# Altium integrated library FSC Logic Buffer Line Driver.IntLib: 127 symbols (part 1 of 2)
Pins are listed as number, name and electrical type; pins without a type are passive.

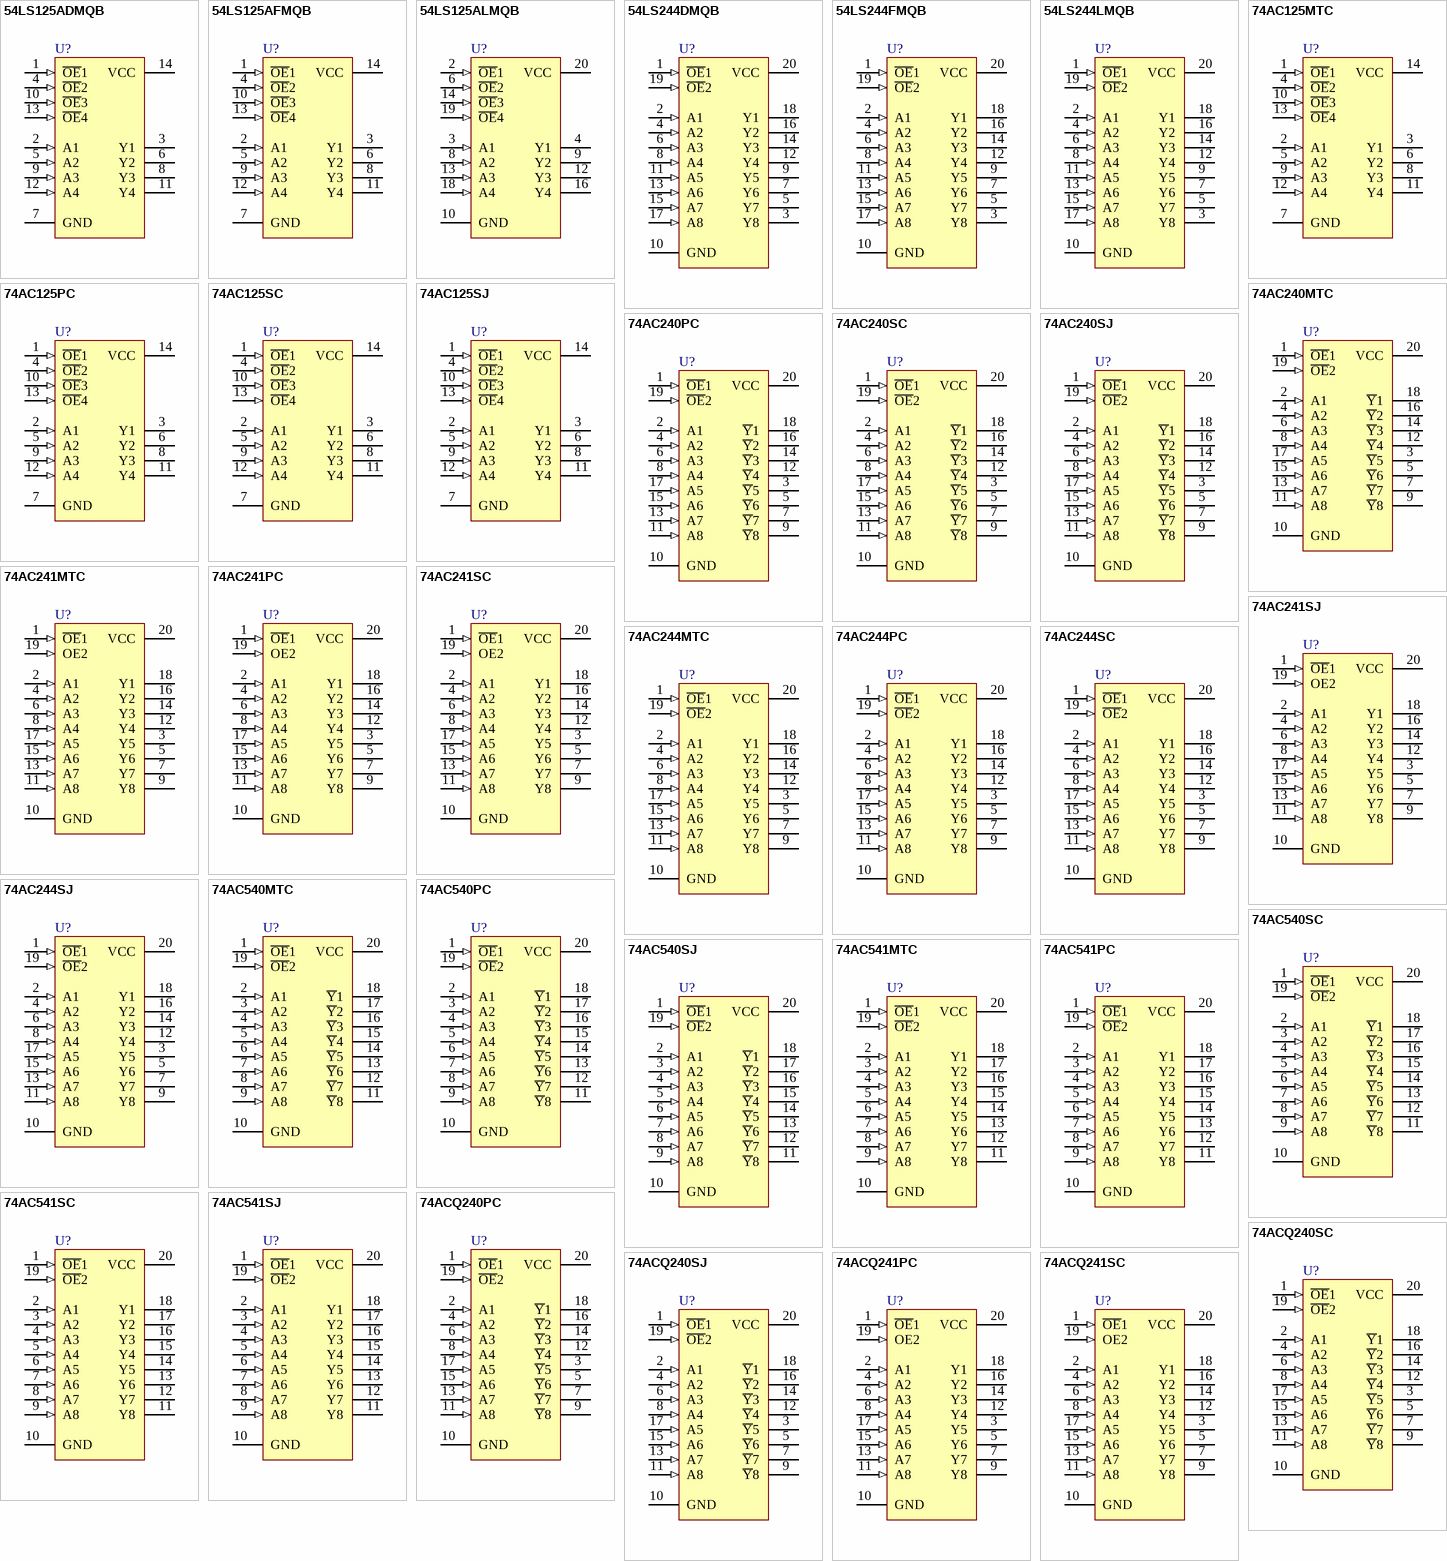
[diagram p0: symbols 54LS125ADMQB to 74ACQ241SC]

## 54LS125ADMQB
designator U?
Quad 3-State Buffer
footprint J14A (DIP, 14-Leads, Row Spacing 7.62mm, Pitch 2.54mm, Body 19.56x6.73mm)
3D model J14A (CerDIP, 14-Pin, Row Spacing 7.62 mm, Pitch 2.54 mm)
simulation model 74LS125 (SIMCODE)
signal-integrity model 54LS125ADMQB
pins: 1 ~{OE}1 (in), 2 A1 (in), 3 Y1 (hiz), 4 ~{OE}2 (in), 5 A2 (in), 6 Y2 (hiz), 7 GND (power), 8 Y3 (hiz), 9 A3 (in), 10 ~{OE}3 (in), 11 Y4 (hiz), 12 A4 (in), 13 ~{OE}4 (in), 14 VCC (power)

## 54LS125AFMQB
designator U?
Quad 3-State Buffer
footprint W14B (DFP; 14 Leads; Body 9.8 x 7.1 mm (LxW max); Pitch 1.27 mm)
3D model W14B (DFP; 14 Leads; Body 9.8 x 7.1 mm (LxW max); Pitch 1.27 mm)
simulation model 74LS125 (SIMCODE)
signal-integrity model 54LS125AFMQB
pins: 1 ~{OE}1 (in), 2 A1 (in), 3 Y1 (hiz), 4 ~{OE}2 (in), 5 A2 (in), 6 Y2 (hiz), 7 GND (power), 8 Y3 (hiz), 9 A3 (in), 10 ~{OE}3 (in), 11 Y4 (hiz), 12 A4 (in), 13 ~{OE}4 (in), 14 VCC (power)

## 54LS125ALMQB
designator U?
Quad 3-State Buffer
footprint E20A (Leadless Chip Carrier; 20 Terminals; Body 8.9 x 8.9 mm)
footprint E20A_N (Leadless Chip Carrier, 20-Leads, Body 8.9x8.9mm, Pitch 1.27mm, IPC Medium Density)
footprint E20A_L (Leadless Chip Carrier, 20-Leads, Body 8.9x8.9mm, Pitch 1.27mm, IPC High Density)
footprint E20A_M (Leadless Chip Carrier, 20-Leads, Body 8.9x8.9mm, Pitch 1.27mm, IPC Low Density)
simulation model 74LS125 (SIMCODE)
signal-integrity model 54LS125ALMQB
pins: 2 ~{OE}1 (in), 3 A1 (in), 4 Y1 (hiz), 6 ~{OE}2 (in), 8 A2 (in), 9 Y2 (hiz), 10 GND (power), 12 Y3 (hiz), 13 A3 (in), 14 ~{OE}3 (in), 16 Y4 (hiz), 18 A4 (in), 19 ~{OE}4 (in), 20 VCC (power)

## 54LS244DMQB
designator U?
Octal 3-State Buffer/Line Driver/Line Receiver
footprint J20A (DIP, 20-Leads, Row Spacing 7.62mm, Pitch 2.54mm, Body 24.62x6.73mm)
3D model J20A (CerDIP, 20-Pin, Row Spacing 7.62 mm, Pitch 2.54 mm)
simulation model 74LS244 (SIMCODE)
signal-integrity model 54LS244DMQB
pins: 1 ~{OE}1 (in), 2 A1 (in), 3 Y8 (hiz), 4 A2 (in), 5 Y7 (hiz), 6 A3 (in), 7 Y6 (hiz), 8 A4 (in), 9 Y5 (hiz), 10 GND (power), 11 A5 (in), 12 Y4 (hiz), 13 A6 (in), 14 Y3 (hiz), 15 A7 (in), 16 Y2 (hiz), 17 A8 (in), 18 Y1 (hiz), 19 ~{OE}2 (in), 20 VCC (power)

## 54LS244FMQB
designator U?
Octal 3-State Buffer/Line Driver/Line Receiver
footprint W20A (DFP; 20 Leads; Body 13.7 x 7.2 mm (LxW max); Pitch 1.27 mm)
3D model W20A (DFP; 20 Leads; Body 13.7 x 7.2 mm (LxW max); Pitch 1.27 mm)
simulation model 74LS244 (SIMCODE)
signal-integrity model 54LS244FMQB
pins: 1 ~{OE}1 (in), 2 A1 (in), 3 Y8 (hiz), 4 A2 (in), 5 Y7 (hiz), 6 A3 (in), 7 Y6 (hiz), 8 A4 (in), 9 Y5 (hiz), 10 GND (power), 11 A5 (in), 12 Y4 (hiz), 13 A6 (in), 14 Y3 (hiz), 15 A7 (in), 16 Y2 (hiz), 17 A8 (in), 18 Y1 (hiz), 19 ~{OE}2 (in), 20 VCC (power)

## 54LS244LMQB
designator U?
Octal 3-State Buffer/Line Driver/Line Receiver
footprint E20A (Leadless Chip Carrier; 20 Terminals; Body 8.9 x 8.9 mm)
footprint E20A_N (Leadless Chip Carrier, 20-Leads, Body 8.9x8.9mm, Pitch 1.27mm, IPC Medium Density)
footprint E20A_L (Leadless Chip Carrier, 20-Leads, Body 8.9x8.9mm, Pitch 1.27mm, IPC High Density)
footprint E20A_M (Leadless Chip Carrier, 20-Leads, Body 8.9x8.9mm, Pitch 1.27mm, IPC Low Density)
simulation model 74LS244 (SIMCODE)
signal-integrity model 54LS244LMQB
pins: 1 ~{OE}1 (in), 2 A1 (in), 3 Y8 (hiz), 4 A2 (in), 5 Y7 (hiz), 6 A3 (in), 7 Y6 (hiz), 8 A4 (in), 9 Y5 (hiz), 10 GND (power), 11 A5 (in), 12 Y4 (hiz), 13 A6 (in), 14 Y3 (hiz), 15 A7 (in), 16 Y2 (hiz), 17 A8 (in), 18 Y1 (hiz), 19 ~{OE}2 (in), 20 VCC (power)

## 74AC125MTC
designator U?
Quad Buffer with 3-State Output
footprint MTC14_N (TSOP, 14-Leads, Body 5x4.4mm, Pitch 0.65mm, IPC Medium Density)
footprint MTC14_L (TSOP, 14-Leads, Body 5x4.4mm, Pitch 0.65mm, IPC High Density)
footprint MTC14_M (TSOP, 14-Leads, Body 5x4.4mm, Pitch 0.65mm, IPC Low Density)
3D model MTC14 (14-Pin Thin Small Outline Package 0.65 mm Pitch)
signal-integrity model 74AC125MTC
pins: 1 ~{OE}1 (in), 2 A1 (in), 3 Y1 (hiz), 4 ~{OE}2 (in), 5 A2 (in), 6 Y2 (hiz), 7 GND (power), 8 Y3 (hiz), 9 A3 (in), 10 ~{OE}3 (in), 11 Y4 (hiz), 12 A4 (in), 13 ~{OE}4 (in), 14 VCC (power)

## 74AC125PC
designator U?
Quad Buffer with 3-State Output
footprint N14A (DIP, 14-Leads, Row Spacing 7.62mm, Pitch 2.54mm, Body 19.18x6.35mm)
3D model N14A (DIP, 14-Pin, Row Spacing 7.62 mm, Pitch 2.54 mm)
signal-integrity model 74AC125PC
pins: 1 ~{OE}1 (in), 2 A1 (in), 3 Y1 (hiz), 4 ~{OE}2 (in), 5 A2 (in), 6 Y2 (hiz), 7 GND (power), 8 Y3 (hiz), 9 A3 (in), 10 ~{OE}3 (in), 11 Y4 (hiz), 12 A4 (in), 13 ~{OE}4 (in), 14 VCC (power)

## 74AC125SC
designator U?
Quad Buffer with 3-State Output
footprint M14A_N (SOIC, 14-Leads, Body 8.6x3.9mm, Pitch 1.27mm, IPC Medium Density)
footprint M14A_L (SOIC, 14-Leads, Body 8.6x3.9mm, Pitch 1.27mm, IPC High Density)
footprint M14A_M (SOIC, 14-Leads, Body 8.6x3.9mm, Pitch 1.27mm, IPC Low Density)
3D model M14A (14-Pin Small Outline Integrated Circuit 1.27 mm Pitch)
signal-integrity model 74AC125SC
pins: 1 ~{OE}1 (in), 2 A1 (in), 3 Y1 (hiz), 4 ~{OE}2 (in), 5 A2 (in), 6 Y2 (hiz), 7 GND (power), 8 Y3 (hiz), 9 A3 (in), 10 ~{OE}3 (in), 11 Y4 (hiz), 12 A4 (in), 13 ~{OE}4 (in), 14 VCC (power)

## 74AC125SJ
designator U?
Quad Buffer with 3-State Output
footprint M14D_N (SOP, 14-Leads, Body 10.1x5.3mm, Pitch 1.27mm, IPC Medium Density)
footprint M14D_L (SOP, 14-Leads, Body 10.1x5.3mm, Pitch 1.27mm, IPC High Density)
footprint M14D_M (SOP, 14-Leads, Body 10.1x5.3mm, Pitch 1.27mm, IPC Low Density)
3D model M14D (14-Pin Small Outline Package 1.27 mm Pitch)
signal-integrity model 74AC125SJ
pins: 1 ~{OE}1 (in), 2 A1 (in), 3 Y1 (hiz), 4 ~{OE}2 (in), 5 A2 (in), 6 Y2 (hiz), 7 GND (power), 8 Y3 (hiz), 9 A3 (in), 10 ~{OE}3 (in), 11 Y4 (hiz), 12 A4 (in), 13 ~{OE}4 (in), 14 VCC (power)

## 74AC240MTC
designator U?
Octal Buffer/Line Driver with 3-State Output
footprint MTC20_N (TSOP, 20-Leads, Body 6.5x4.4mm, Pitch 0.65mm, IPC Medium Density)
footprint MTC20_L (TSOP, 20-Leads, Body 6.5x4.4mm, Pitch 0.65mm, IPC High Density)
footprint MTC20_M (TSOP, 20-Leads, Body 6.5x4.4mm, Pitch 0.65mm, IPC Low Density)
3D model MTC20 (20-Pin Thin Small Outline Package 0.65 mm Pitch)
signal-integrity model 74AC240MTC
pins: 1 ~{OE}1 (in), 2 A1 (in), 3 ~{Y}5 (hiz), 4 A2 (in), 5 ~{Y}6 (hiz), 6 A3 (in), 7 ~{Y}7 (hiz), 8 A4 (in), 9 ~{Y}8 (hiz), 10 GND (power), 11 A8 (in), 12 ~{Y}4 (hiz), 13 A7 (in), 14 ~{Y}3 (hiz), 15 A6 (in), 16 ~{Y}2 (hiz), 17 A5 (in), 18 ~{Y}1 (hiz), 19 ~{OE}2 (in), 20 VCC (power)

## 74AC240PC
designator U?
Octal Buffer/Line Driver with 3-State Output
footprint N20A (DIP, 20-Leads, Row Spacing 7.62mm, Pitch 2.54mm, Body 26.07x6.6mm)
3D model N20A (DIP, 20-Pin, Row Spacing 7.62 mm, Pitch 2.54 mm)
signal-integrity model 74AC240PC
pins: 1 ~{OE}1 (in), 2 A1 (in), 3 ~{Y}5 (hiz), 4 A2 (in), 5 ~{Y}6 (hiz), 6 A3 (in), 7 ~{Y}7 (hiz), 8 A4 (in), 9 ~{Y}8 (hiz), 10 GND (power), 11 A8 (in), 12 ~{Y}4 (hiz), 13 A7 (in), 14 ~{Y}3 (hiz), 15 A6 (in), 16 ~{Y}2 (hiz), 17 A5 (in), 18 ~{Y}1 (hiz), 19 ~{OE}2 (in), 20 VCC (power)

## 74AC240SC
designator U?
Octal Buffer/Line Driver with 3-State Output
footprint M20B_N (SOIC, 20-Leads, Body 12.8x7.5mm, Pitch 1.27mm, IPC Medium Density)
footprint M20B_L (SOIC, 20-Leads, Body 12.8x7.5mm, Pitch 1.27mm, IPC High Density)
footprint M20B_M (SOIC, 20-Leads, Body 12.8x7.5mm, Pitch 1.27mm, IPC Low Density)
3D model M20B (20-Pin Small Outline Integrated Circuit 1.27 mm Pitch)
signal-integrity model 74AC240SC
pins: 1 ~{OE}1 (in), 2 A1 (in), 3 ~{Y}5 (hiz), 4 A2 (in), 5 ~{Y}6 (hiz), 6 A3 (in), 7 ~{Y}7 (hiz), 8 A4 (in), 9 ~{Y}8 (hiz), 10 GND (power), 11 A8 (in), 12 ~{Y}4 (hiz), 13 A7 (in), 14 ~{Y}3 (hiz), 15 A6 (in), 16 ~{Y}2 (hiz), 17 A5 (in), 18 ~{Y}1 (hiz), 19 ~{OE}2 (in), 20 VCC (power)

## 74AC240SJ
designator U?
Octal Buffer/Line Driver with 3-State Output
footprint M20D_N (SOP, 20-Leads, Body 12.6x5.3mm, Pitch 1.27mm, IPC Medium Density)
footprint M20D_L (SOP, 20-Leads, Body 12.6x5.3mm, Pitch 1.27mm, IPC High Density)
footprint M20D_M (SOP, 20-Leads, Body 12.6x5.3mm, Pitch 1.27mm, IPC Low Density)
3D model M20D (20-Pin Small Outline Package 1.27 mm Pitch)
signal-integrity model 74AC240SJ
pins: 1 ~{OE}1 (in), 2 A1 (in), 3 ~{Y}5 (hiz), 4 A2 (in), 5 ~{Y}6 (hiz), 6 A3 (in), 7 ~{Y}7 (hiz), 8 A4 (in), 9 ~{Y}8 (hiz), 10 GND (power), 11 A8 (in), 12 ~{Y}4 (hiz), 13 A7 (in), 14 ~{Y}3 (hiz), 15 A6 (in), 16 ~{Y}2 (hiz), 17 A5 (in), 18 ~{Y}1 (hiz), 19 ~{OE}2 (in), 20 VCC (power)

## 74AC241MTC
designator U?
Octal Buffer/Line Driver with 3-State Output
footprint MTC20_N (TSOP, 20-Leads, Body 6.5x4.4mm, Pitch 0.65mm, IPC Medium Density)
footprint MTC20_L (TSOP, 20-Leads, Body 6.5x4.4mm, Pitch 0.65mm, IPC High Density)
footprint MTC20_M (TSOP, 20-Leads, Body 6.5x4.4mm, Pitch 0.65mm, IPC Low Density)
3D model MTC20 (20-Pin Thin Small Outline Package 0.65 mm Pitch)
signal-integrity model 74AC241MTC
pins: 1 ~{OE}1 (in), 2 A1 (in), 3 Y5 (hiz), 4 A2 (in), 5 Y6 (hiz), 6 A3 (in), 7 Y7 (hiz), 8 A4 (in), 9 Y8 (hiz), 10 GND (power), 11 A8 (in), 12 Y4 (hiz), 13 A7 (in), 14 Y3 (hiz), 15 A6 (in), 16 Y2 (hiz), 17 A5 (in), 18 Y1 (hiz), 19 OE2 (in), 20 VCC (power)

## 74AC241PC
designator U?
Octal Buffer/Line Driver with 3-State Output
footprint N20A (DIP, 20-Leads, Row Spacing 7.62mm, Pitch 2.54mm, Body 26.07x6.6mm)
3D model N20A (DIP, 20-Pin, Row Spacing 7.62 mm, Pitch 2.54 mm)
signal-integrity model 74AC241PC
pins: 1 ~{OE}1 (in), 2 A1 (in), 3 Y5 (hiz), 4 A2 (in), 5 Y6 (hiz), 6 A3 (in), 7 Y7 (hiz), 8 A4 (in), 9 Y8 (hiz), 10 GND (power), 11 A8 (in), 12 Y4 (hiz), 13 A7 (in), 14 Y3 (hiz), 15 A6 (in), 16 Y2 (hiz), 17 A5 (in), 18 Y1 (hiz), 19 OE2 (in), 20 VCC (power)

## 74AC241SC
designator U?
Octal Buffer/Line Driver with 3-State Output
footprint M20B_N (SOIC, 20-Leads, Body 12.8x7.5mm, Pitch 1.27mm, IPC Medium Density)
footprint M20B_L (SOIC, 20-Leads, Body 12.8x7.5mm, Pitch 1.27mm, IPC High Density)
footprint M20B_M (SOIC, 20-Leads, Body 12.8x7.5mm, Pitch 1.27mm, IPC Low Density)
3D model M20B (20-Pin Small Outline Integrated Circuit 1.27 mm Pitch)
signal-integrity model 74AC241SC
pins: 1 ~{OE}1 (in), 2 A1 (in), 3 Y5 (hiz), 4 A2 (in), 5 Y6 (hiz), 6 A3 (in), 7 Y7 (hiz), 8 A4 (in), 9 Y8 (hiz), 10 GND (power), 11 A8 (in), 12 Y4 (hiz), 13 A7 (in), 14 Y3 (hiz), 15 A6 (in), 16 Y2 (hiz), 17 A5 (in), 18 Y1 (hiz), 19 OE2 (in), 20 VCC (power)

## 74AC241SJ
designator U?
Octal Buffer/Line Driver with 3-State Output
footprint M20D_N (SOP, 20-Leads, Body 12.6x5.3mm, Pitch 1.27mm, IPC Medium Density)
footprint M20D_L (SOP, 20-Leads, Body 12.6x5.3mm, Pitch 1.27mm, IPC High Density)
footprint M20D_M (SOP, 20-Leads, Body 12.6x5.3mm, Pitch 1.27mm, IPC Low Density)
3D model M20D (20-Pin Small Outline Package 1.27 mm Pitch)
signal-integrity model 74AC241SJ
pins: 1 ~{OE}1 (in), 2 A1 (in), 3 Y5 (hiz), 4 A2 (in), 5 Y6 (hiz), 6 A3 (in), 7 Y7 (hiz), 8 A4 (in), 9 Y8 (hiz), 10 GND (power), 11 A8 (in), 12 Y4 (hiz), 13 A7 (in), 14 Y3 (hiz), 15 A6 (in), 16 Y2 (hiz), 17 A5 (in), 18 Y1 (hiz), 19 OE2 (in), 20 VCC (power)

## 74AC244MTC
designator U?
Octal Buffer/Line Driver with 3-State Output
footprint MTC20_N (TSOP, 20-Leads, Body 6.5x4.4mm, Pitch 0.65mm, IPC Medium Density)
footprint MTC20_L (TSOP, 20-Leads, Body 6.5x4.4mm, Pitch 0.65mm, IPC High Density)
footprint MTC20_M (TSOP, 20-Leads, Body 6.5x4.4mm, Pitch 0.65mm, IPC Low Density)
3D model MTC20 (20-Pin Thin Small Outline Package 0.65 mm Pitch)
signal-integrity model 74AC244MTC
pins: 1 ~{OE}1 (in), 2 A1 (in), 3 Y5 (hiz), 4 A2 (in), 5 Y6 (hiz), 6 A3 (in), 7 Y7 (hiz), 8 A4 (in), 9 Y8 (hiz), 10 GND (power), 11 A8 (in), 12 Y4 (hiz), 13 A7 (in), 14 Y3 (hiz), 15 A6 (in), 16 Y2 (hiz), 17 A5 (in), 18 Y1 (hiz), 19 ~{OE}2 (in), 20 VCC (power)

## 74AC244PC
designator U?
Octal Buffer/Line Driver with 3-State Output
footprint N20A (DIP, 20-Leads, Row Spacing 7.62mm, Pitch 2.54mm, Body 26.07x6.6mm)
3D model N20A (DIP, 20-Pin, Row Spacing 7.62 mm, Pitch 2.54 mm)
signal-integrity model 74AC244PC
pins: 1 ~{OE}1 (in), 2 A1 (in), 3 Y5 (hiz), 4 A2 (in), 5 Y6 (hiz), 6 A3 (in), 7 Y7 (hiz), 8 A4 (in), 9 Y8 (hiz), 10 GND (power), 11 A8 (in), 12 Y4 (hiz), 13 A7 (in), 14 Y3 (hiz), 15 A6 (in), 16 Y2 (hiz), 17 A5 (in), 18 Y1 (hiz), 19 ~{OE}2 (in), 20 VCC (power)

## 74AC244SC
designator U?
Octal Buffer/Line Driver with 3-State Output
footprint M20B_N (SOIC, 20-Leads, Body 12.8x7.5mm, Pitch 1.27mm, IPC Medium Density)
footprint M20B_L (SOIC, 20-Leads, Body 12.8x7.5mm, Pitch 1.27mm, IPC High Density)
footprint M20B_M (SOIC, 20-Leads, Body 12.8x7.5mm, Pitch 1.27mm, IPC Low Density)
3D model M20B (20-Pin Small Outline Integrated Circuit 1.27 mm Pitch)
signal-integrity model 74AC244SC
pins: 1 ~{OE}1 (in), 2 A1 (in), 3 Y5 (hiz), 4 A2 (in), 5 Y6 (hiz), 6 A3 (in), 7 Y7 (hiz), 8 A4 (in), 9 Y8 (hiz), 10 GND (power), 11 A8 (in), 12 Y4 (hiz), 13 A7 (in), 14 Y3 (hiz), 15 A6 (in), 16 Y2 (hiz), 17 A5 (in), 18 Y1 (hiz), 19 ~{OE}2 (in), 20 VCC (power)

## 74AC244SJ
designator U?
Octal Buffer/Line Driver with 3-State Output
footprint M20D_N (SOP, 20-Leads, Body 12.6x5.3mm, Pitch 1.27mm, IPC Medium Density)
footprint M20D_L (SOP, 20-Leads, Body 12.6x5.3mm, Pitch 1.27mm, IPC High Density)
footprint M20D_M (SOP, 20-Leads, Body 12.6x5.3mm, Pitch 1.27mm, IPC Low Density)
3D model M20D (20-Pin Small Outline Package 1.27 mm Pitch)
signal-integrity model 74AC244SJ
pins: 1 ~{OE}1 (in), 2 A1 (in), 3 Y5 (hiz), 4 A2 (in), 5 Y6 (hiz), 6 A3 (in), 7 Y7 (hiz), 8 A4 (in), 9 Y8 (hiz), 10 GND (power), 11 A8 (in), 12 Y4 (hiz), 13 A7 (in), 14 Y3 (hiz), 15 A6 (in), 16 Y2 (hiz), 17 A5 (in), 18 Y1 (hiz), 19 ~{OE}2 (in), 20 VCC (power)

## 74AC540MTC
designator U?
Octal Buffer/Line Driver with 3-State Output
footprint MTC20_N (TSOP, 20-Leads, Body 6.5x4.4mm, Pitch 0.65mm, IPC Medium Density)
footprint MTC20_L (TSOP, 20-Leads, Body 6.5x4.4mm, Pitch 0.65mm, IPC High Density)
footprint MTC20_M (TSOP, 20-Leads, Body 6.5x4.4mm, Pitch 0.65mm, IPC Low Density)
3D model MTC20 (20-Pin Thin Small Outline Package 0.65 mm Pitch)
signal-integrity model 74AC540MTC
pins: 1 ~{OE}1 (in), 2 A1 (in), 3 A2 (in), 4 A3 (in), 5 A4 (in), 6 A5 (in), 7 A6 (in), 8 A7 (in), 9 A8 (in), 10 GND (power), 11 ~{Y}8 (hiz), 12 ~{Y}7 (hiz), 13 ~{Y}6 (hiz), 14 ~{Y}5 (hiz), 15 ~{Y}4 (hiz), 16 ~{Y}3 (hiz), 17 ~{Y}2 (hiz), 18 ~{Y}1 (hiz), 19 ~{OE}2 (in), 20 VCC (power)

## 74AC540PC
designator U?
Octal Buffer/Line Driver with 3-State Output
footprint N20A (DIP, 20-Leads, Row Spacing 7.62mm, Pitch 2.54mm, Body 26.07x6.6mm)
3D model N20A (DIP, 20-Pin, Row Spacing 7.62 mm, Pitch 2.54 mm)
signal-integrity model 74AC540PC
pins: 1 ~{OE}1 (in), 2 A1 (in), 3 A2 (in), 4 A3 (in), 5 A4 (in), 6 A5 (in), 7 A6 (in), 8 A7 (in), 9 A8 (in), 10 GND (power), 11 ~{Y}8 (hiz), 12 ~{Y}7 (hiz), 13 ~{Y}6 (hiz), 14 ~{Y}5 (hiz), 15 ~{Y}4 (hiz), 16 ~{Y}3 (hiz), 17 ~{Y}2 (hiz), 18 ~{Y}1 (hiz), 19 ~{OE}2 (in), 20 VCC (power)

## 74AC540SC
designator U?
Octal Buffer/Line Driver with 3-State Output
footprint M20B_N (SOIC, 20-Leads, Body 12.8x7.5mm, Pitch 1.27mm, IPC Medium Density)
footprint M20B_L (SOIC, 20-Leads, Body 12.8x7.5mm, Pitch 1.27mm, IPC High Density)
footprint M20B_M (SOIC, 20-Leads, Body 12.8x7.5mm, Pitch 1.27mm, IPC Low Density)
3D model M20B (20-Pin Small Outline Integrated Circuit 1.27 mm Pitch)
signal-integrity model 74AC540SC
pins: 1 ~{OE}1 (in), 2 A1 (in), 3 A2 (in), 4 A3 (in), 5 A4 (in), 6 A5 (in), 7 A6 (in), 8 A7 (in), 9 A8 (in), 10 GND (power), 11 ~{Y}8 (hiz), 12 ~{Y}7 (hiz), 13 ~{Y}6 (hiz), 14 ~{Y}5 (hiz), 15 ~{Y}4 (hiz), 16 ~{Y}3 (hiz), 17 ~{Y}2 (hiz), 18 ~{Y}1 (hiz), 19 ~{OE}2 (in), 20 VCC (power)

## 74AC540SJ
designator U?
Octal Buffer/Line Driver with 3-State Output
footprint M20D_N (SOP, 20-Leads, Body 12.6x5.3mm, Pitch 1.27mm, IPC Medium Density)
footprint M20D_L (SOP, 20-Leads, Body 12.6x5.3mm, Pitch 1.27mm, IPC High Density)
footprint M20D_M (SOP, 20-Leads, Body 12.6x5.3mm, Pitch 1.27mm, IPC Low Density)
3D model M20D (20-Pin Small Outline Package 1.27 mm Pitch)
signal-integrity model 74AC540SJ
pins: 1 ~{OE}1 (in), 2 A1 (in), 3 A2 (in), 4 A3 (in), 5 A4 (in), 6 A5 (in), 7 A6 (in), 8 A7 (in), 9 A8 (in), 10 GND (power), 11 ~{Y}8 (hiz), 12 ~{Y}7 (hiz), 13 ~{Y}6 (hiz), 14 ~{Y}5 (hiz), 15 ~{Y}4 (hiz), 16 ~{Y}3 (hiz), 17 ~{Y}2 (hiz), 18 ~{Y}1 (hiz), 19 ~{OE}2 (in), 20 VCC (power)

## 74AC541MTC
designator U?
Octal Buffer/Line Driver with 3-State Output
footprint MTC20_N (TSOP, 20-Leads, Body 6.5x4.4mm, Pitch 0.65mm, IPC Medium Density)
footprint MTC20_L (TSOP, 20-Leads, Body 6.5x4.4mm, Pitch 0.65mm, IPC High Density)
footprint MTC20_M (TSOP, 20-Leads, Body 6.5x4.4mm, Pitch 0.65mm, IPC Low Density)
3D model MTC20 (20-Pin Thin Small Outline Package 0.65 mm Pitch)
signal-integrity model 74AC541MTC
pins: 1 ~{OE}1 (in), 2 A1 (in), 3 A2 (in), 4 A3 (in), 5 A4 (in), 6 A5 (in), 7 A6 (in), 8 A7 (in), 9 A8 (in), 10 GND (power), 11 Y8 (hiz), 12 Y7 (hiz), 13 Y6 (hiz), 14 Y5 (hiz), 15 Y4 (hiz), 16 Y3 (hiz), 17 Y2 (hiz), 18 Y1 (hiz), 19 ~{OE}2 (in), 20 VCC (power)

## 74AC541PC
designator U?
Octal Buffer/Line Driver with 3-State Output
footprint N20A (DIP, 20-Leads, Row Spacing 7.62mm, Pitch 2.54mm, Body 26.07x6.6mm)
3D model N20A (DIP, 20-Pin, Row Spacing 7.62 mm, Pitch 2.54 mm)
signal-integrity model 74AC541PC
pins: 1 ~{OE}1 (in), 2 A1 (in), 3 A2 (in), 4 A3 (in), 5 A4 (in), 6 A5 (in), 7 A6 (in), 8 A7 (in), 9 A8 (in), 10 GND (power), 11 Y8 (hiz), 12 Y7 (hiz), 13 Y6 (hiz), 14 Y5 (hiz), 15 Y4 (hiz), 16 Y3 (hiz), 17 Y2 (hiz), 18 Y1 (hiz), 19 ~{OE}2 (in), 20 VCC (power)

## 74AC541SC
designator U?
Octal Buffer/Line Driver with 3-State Output
footprint M20B_N (SOIC, 20-Leads, Body 12.8x7.5mm, Pitch 1.27mm, IPC Medium Density)
footprint M20B_L (SOIC, 20-Leads, Body 12.8x7.5mm, Pitch 1.27mm, IPC High Density)
footprint M20B_M (SOIC, 20-Leads, Body 12.8x7.5mm, Pitch 1.27mm, IPC Low Density)
3D model M20B (20-Pin Small Outline Integrated Circuit 1.27 mm Pitch)
signal-integrity model 74AC541SC
pins: 1 ~{OE}1 (in), 2 A1 (in), 3 A2 (in), 4 A3 (in), 5 A4 (in), 6 A5 (in), 7 A6 (in), 8 A7 (in), 9 A8 (in), 10 GND (power), 11 Y8 (hiz), 12 Y7 (hiz), 13 Y6 (hiz), 14 Y5 (hiz), 15 Y4 (hiz), 16 Y3 (hiz), 17 Y2 (hiz), 18 Y1 (hiz), 19 ~{OE}2 (in), 20 VCC (power)

## 74AC541SJ
designator U?
Octal Buffer/Line Driver with 3-State Output
footprint M20D_N (SOP, 20-Leads, Body 12.6x5.3mm, Pitch 1.27mm, IPC Medium Density)
footprint M20D_L (SOP, 20-Leads, Body 12.6x5.3mm, Pitch 1.27mm, IPC High Density)
footprint M20D_M (SOP, 20-Leads, Body 12.6x5.3mm, Pitch 1.27mm, IPC Low Density)
3D model M20D (20-Pin Small Outline Package 1.27 mm Pitch)
signal-integrity model 74AC541SJ
pins: 1 ~{OE}1 (in), 2 A1 (in), 3 A2 (in), 4 A3 (in), 5 A4 (in), 6 A5 (in), 7 A6 (in), 8 A7 (in), 9 A8 (in), 10 GND (power), 11 Y8 (hiz), 12 Y7 (hiz), 13 Y6 (hiz), 14 Y5 (hiz), 15 Y4 (hiz), 16 Y3 (hiz), 17 Y2 (hiz), 18 Y1 (hiz), 19 ~{OE}2 (in), 20 VCC (power)

## 74ACQ240PC
designator U?
Octal Buffer/Line Driver with 3-State Output
footprint N20A (DIP, 20-Leads, Row Spacing 7.62mm, Pitch 2.54mm, Body 26.07x6.6mm)
3D model N20A (DIP, 20-Pin, Row Spacing 7.62 mm, Pitch 2.54 mm)
pins: 1 ~{OE}1 (in), 2 A1 (in), 3 ~{Y}5 (hiz), 4 A2 (in), 5 ~{Y}6 (hiz), 6 A3 (in), 7 ~{Y}7 (hiz), 8 A4 (in), 9 ~{Y}8 (hiz), 10 GND (power), 11 A8 (in), 12 ~{Y}4 (hiz), 13 A7 (in), 14 ~{Y}3 (hiz), 15 A6 (in), 16 ~{Y}2 (hiz), 17 A5 (in), 18 ~{Y}1 (hiz), 19 ~{OE}2 (in), 20 VCC (power)

## 74ACQ240SC
designator U?
Octal Buffer/Line Driver with 3-State Output
footprint M20B_N (SOIC, 20-Leads, Body 12.8x7.5mm, Pitch 1.27mm, IPC Medium Density)
footprint M20B_L (SOIC, 20-Leads, Body 12.8x7.5mm, Pitch 1.27mm, IPC High Density)
footprint M20B_M (SOIC, 20-Leads, Body 12.8x7.5mm, Pitch 1.27mm, IPC Low Density)
3D model M20B (20-Pin Small Outline Integrated Circuit 1.27 mm Pitch)
pins: 1 ~{OE}1 (in), 2 A1 (in), 3 ~{Y}5 (hiz), 4 A2 (in), 5 ~{Y}6 (hiz), 6 A3 (in), 7 ~{Y}7 (hiz), 8 A4 (in), 9 ~{Y}8 (hiz), 10 GND (power), 11 A8 (in), 12 ~{Y}4 (hiz), 13 A7 (in), 14 ~{Y}3 (hiz), 15 A6 (in), 16 ~{Y}2 (hiz), 17 A5 (in), 18 ~{Y}1 (hiz), 19 ~{OE}2 (in), 20 VCC (power)

## 74ACQ240SJ
designator U?
Octal Buffer/Line Driver with 3-State Output
footprint M20D_N (SOP, 20-Leads, Body 12.6x5.3mm, Pitch 1.27mm, IPC Medium Density)
footprint M20D_L (SOP, 20-Leads, Body 12.6x5.3mm, Pitch 1.27mm, IPC High Density)
footprint M20D_M (SOP, 20-Leads, Body 12.6x5.3mm, Pitch 1.27mm, IPC Low Density)
3D model M20D (20-Pin Small Outline Package 1.27 mm Pitch)
pins: 1 ~{OE}1 (in), 2 A1 (in), 3 ~{Y}5 (hiz), 4 A2 (in), 5 ~{Y}6 (hiz), 6 A3 (in), 7 ~{Y}7 (hiz), 8 A4 (in), 9 ~{Y}8 (hiz), 10 GND (power), 11 A8 (in), 12 ~{Y}4 (hiz), 13 A7 (in), 14 ~{Y}3 (hiz), 15 A6 (in), 16 ~{Y}2 (hiz), 17 A5 (in), 18 ~{Y}1 (hiz), 19 ~{OE}2 (in), 20 VCC (power)

## 74ACQ241PC
designator U?
Octal Buffer/Line Driver with 3-State Output
footprint N20A (DIP, 20-Leads, Row Spacing 7.62mm, Pitch 2.54mm, Body 26.07x6.6mm)
3D model N20A (DIP, 20-Pin, Row Spacing 7.62 mm, Pitch 2.54 mm)
pins: 1 ~{OE}1 (in), 2 A1 (in), 3 Y5 (hiz), 4 A2 (in), 5 Y6 (hiz), 6 A3 (in), 7 Y7 (hiz), 8 A4 (in), 9 Y8 (hiz), 10 GND (power), 11 A8 (in), 12 Y4 (hiz), 13 A7 (in), 14 Y3 (hiz), 15 A6 (in), 16 Y2 (hiz), 17 A5 (in), 18 Y1 (hiz), 19 OE2 (in), 20 VCC (power)

## 74ACQ241SC
designator U?
Octal Buffer/Line Driver with 3-State Output
footprint M20B_N (SOIC, 20-Leads, Body 12.8x7.5mm, Pitch 1.27mm, IPC Medium Density)
footprint M20B_L (SOIC, 20-Leads, Body 12.8x7.5mm, Pitch 1.27mm, IPC High Density)
footprint M20B_M (SOIC, 20-Leads, Body 12.8x7.5mm, Pitch 1.27mm, IPC Low Density)
3D model M20B (20-Pin Small Outline Integrated Circuit 1.27 mm Pitch)
pins: 1 ~{OE}1 (in), 2 A1 (in), 3 Y5 (hiz), 4 A2 (in), 5 Y6 (hiz), 6 A3 (in), 7 Y7 (hiz), 8 A4 (in), 9 Y8 (hiz), 10 GND (power), 11 A8 (in), 12 Y4 (hiz), 13 A7 (in), 14 Y3 (hiz), 15 A6 (in), 16 Y2 (hiz), 17 A5 (in), 18 Y1 (hiz), 19 OE2 (in), 20 VCC (power)

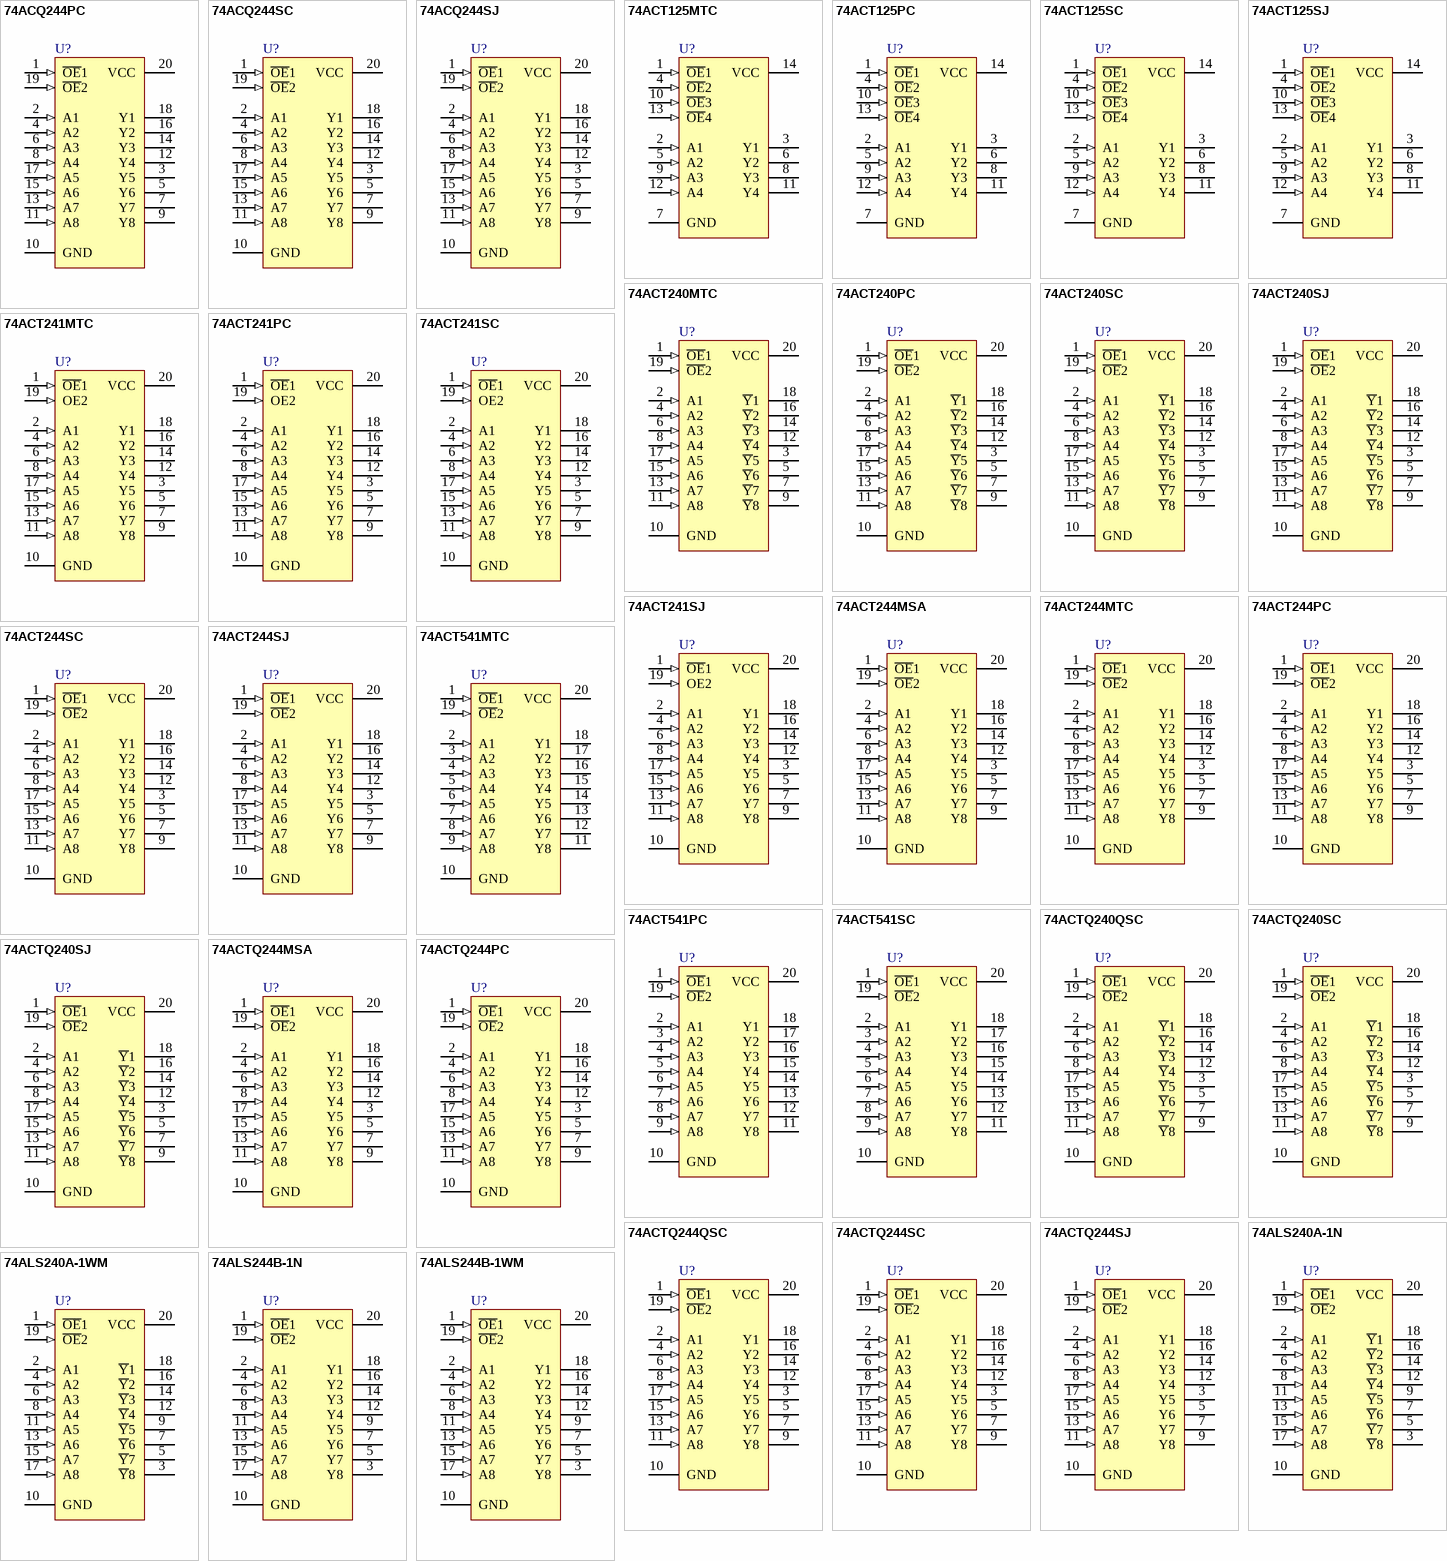
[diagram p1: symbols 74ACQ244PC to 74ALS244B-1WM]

## 74ACQ244PC
designator U?
Octal Buffer/Line Driver with 3-State Output
footprint N20A (DIP, 20-Leads, Row Spacing 7.62mm, Pitch 2.54mm, Body 26.07x6.6mm)
3D model N20A (DIP, 20-Pin, Row Spacing 7.62 mm, Pitch 2.54 mm)
pins: 1 ~{OE}1 (in), 2 A1 (in), 3 Y5 (hiz), 4 A2 (in), 5 Y6 (hiz), 6 A3 (in), 7 Y7 (hiz), 8 A4 (in), 9 Y8 (hiz), 10 GND (power), 11 A8 (in), 12 Y4 (hiz), 13 A7 (in), 14 Y3 (hiz), 15 A6 (in), 16 Y2 (hiz), 17 A5 (in), 18 Y1 (hiz), 19 ~{OE}2 (in), 20 VCC (power)

## 74ACQ244SC
designator U?
Octal Buffer/Line Driver with 3-State Output
footprint M20B_N (SOIC, 20-Leads, Body 12.8x7.5mm, Pitch 1.27mm, IPC Medium Density)
footprint M20B_L (SOIC, 20-Leads, Body 12.8x7.5mm, Pitch 1.27mm, IPC High Density)
footprint M20B_M (SOIC, 20-Leads, Body 12.8x7.5mm, Pitch 1.27mm, IPC Low Density)
3D model M20B (20-Pin Small Outline Integrated Circuit 1.27 mm Pitch)
pins: 1 ~{OE}1 (in), 2 A1 (in), 3 Y5 (hiz), 4 A2 (in), 5 Y6 (hiz), 6 A3 (in), 7 Y7 (hiz), 8 A4 (in), 9 Y8 (hiz), 10 GND (power), 11 A8 (in), 12 Y4 (hiz), 13 A7 (in), 14 Y3 (hiz), 15 A6 (in), 16 Y2 (hiz), 17 A5 (in), 18 Y1 (hiz), 19 ~{OE}2 (in), 20 VCC (power)

## 74ACQ244SJ
designator U?
Octal Buffer/Line Driver with 3-State Output
footprint M20D_N (SOP, 20-Leads, Body 12.6x5.3mm, Pitch 1.27mm, IPC Medium Density)
footprint M20D_L (SOP, 20-Leads, Body 12.6x5.3mm, Pitch 1.27mm, IPC High Density)
footprint M20D_M (SOP, 20-Leads, Body 12.6x5.3mm, Pitch 1.27mm, IPC Low Density)
3D model M20D (20-Pin Small Outline Package 1.27 mm Pitch)
pins: 1 ~{OE}1 (in), 2 A1 (in), 3 Y5 (hiz), 4 A2 (in), 5 Y6 (hiz), 6 A3 (in), 7 Y7 (hiz), 8 A4 (in), 9 Y8 (hiz), 10 GND (power), 11 A8 (in), 12 Y4 (hiz), 13 A7 (in), 14 Y3 (hiz), 15 A6 (in), 16 Y2 (hiz), 17 A5 (in), 18 Y1 (hiz), 19 ~{OE}2 (in), 20 VCC (power)

## 74ACT125MTC
designator U?
Quad Buffer with 3-State Output
footprint MTC14_N (TSOP, 14-Leads, Body 5x4.4mm, Pitch 0.65mm, IPC Medium Density)
footprint MTC14_L (TSOP, 14-Leads, Body 5x4.4mm, Pitch 0.65mm, IPC High Density)
footprint MTC14_M (TSOP, 14-Leads, Body 5x4.4mm, Pitch 0.65mm, IPC Low Density)
3D model MTC14 (14-Pin Thin Small Outline Package 0.65 mm Pitch)
signal-integrity model 74ACT125MTC
pins: 1 ~{OE}1 (in), 2 A1 (in), 3 Y1 (hiz), 4 ~{OE}2 (in), 5 A2 (in), 6 Y2 (hiz), 7 GND (power), 8 Y3 (hiz), 9 A3 (in), 10 ~{OE}3 (in), 11 Y4 (hiz), 12 A4 (in), 13 ~{OE}4 (in), 14 VCC (power)

## 74ACT125PC
designator U?
Quad Buffer with 3-State Output
footprint N14A (DIP, 14-Leads, Row Spacing 7.62mm, Pitch 2.54mm, Body 19.18x6.35mm)
3D model N14A (DIP, 14-Pin, Row Spacing 7.62 mm, Pitch 2.54 mm)
signal-integrity model 74ACT125PC
pins: 1 ~{OE}1 (in), 2 A1 (in), 3 Y1 (hiz), 4 ~{OE}2 (in), 5 A2 (in), 6 Y2 (hiz), 7 GND (power), 8 Y3 (hiz), 9 A3 (in), 10 ~{OE}3 (in), 11 Y4 (hiz), 12 A4 (in), 13 ~{OE}4 (in), 14 VCC (power)

## 74ACT125SC
designator U?
Quad Buffer with 3-State Output
footprint M14A_N (SOIC, 14-Leads, Body 8.6x3.9mm, Pitch 1.27mm, IPC Medium Density)
footprint M14A_L (SOIC, 14-Leads, Body 8.6x3.9mm, Pitch 1.27mm, IPC High Density)
footprint M14A_M (SOIC, 14-Leads, Body 8.6x3.9mm, Pitch 1.27mm, IPC Low Density)
3D model M14A (14-Pin Small Outline Integrated Circuit 1.27 mm Pitch)
signal-integrity model 74ACT125SC
pins: 1 ~{OE}1 (in), 2 A1 (in), 3 Y1 (hiz), 4 ~{OE}2 (in), 5 A2 (in), 6 Y2 (hiz), 7 GND (power), 8 Y3 (hiz), 9 A3 (in), 10 ~{OE}3 (in), 11 Y4 (hiz), 12 A4 (in), 13 ~{OE}4 (in), 14 VCC (power)

## 74ACT125SJ
designator U?
Quad Buffer with 3-State Output
footprint M14D_N (SOP, 14-Leads, Body 10.1x5.3mm, Pitch 1.27mm, IPC Medium Density)
footprint M14D_L (SOP, 14-Leads, Body 10.1x5.3mm, Pitch 1.27mm, IPC High Density)
footprint M14D_M (SOP, 14-Leads, Body 10.1x5.3mm, Pitch 1.27mm, IPC Low Density)
3D model M14D (14-Pin Small Outline Package 1.27 mm Pitch)
signal-integrity model 74ACT125SJ
pins: 1 ~{OE}1 (in), 2 A1 (in), 3 Y1 (hiz), 4 ~{OE}2 (in), 5 A2 (in), 6 Y2 (hiz), 7 GND (power), 8 Y3 (hiz), 9 A3 (in), 10 ~{OE}3 (in), 11 Y4 (hiz), 12 A4 (in), 13 ~{OE}4 (in), 14 VCC (power)

## 74ACT240MTC
designator U?
Octal Buffer/Line Driver with 3-State Output
footprint MTC20_N (TSOP, 20-Leads, Body 6.5x4.4mm, Pitch 0.65mm, IPC Medium Density)
footprint MTC20_L (TSOP, 20-Leads, Body 6.5x4.4mm, Pitch 0.65mm, IPC High Density)
footprint MTC20_M (TSOP, 20-Leads, Body 6.5x4.4mm, Pitch 0.65mm, IPC Low Density)
3D model MTC20 (20-Pin Thin Small Outline Package 0.65 mm Pitch)
signal-integrity model 74ACT240MTC
pins: 1 ~{OE}1 (in), 2 A1 (in), 3 ~{Y}5 (hiz), 4 A2 (in), 5 ~{Y}6 (hiz), 6 A3 (in), 7 ~{Y}7 (hiz), 8 A4 (in), 9 ~{Y}8 (hiz), 10 GND (power), 11 A8 (in), 12 ~{Y}4 (hiz), 13 A7 (in), 14 ~{Y}3 (hiz), 15 A6 (in), 16 ~{Y}2 (hiz), 17 A5 (in), 18 ~{Y}1 (hiz), 19 ~{OE}2 (in), 20 VCC (power)

## 74ACT240PC
designator U?
Octal Buffer/Line Driver with 3-State Output
footprint N20A (DIP, 20-Leads, Row Spacing 7.62mm, Pitch 2.54mm, Body 26.07x6.6mm)
3D model N20A (DIP, 20-Pin, Row Spacing 7.62 mm, Pitch 2.54 mm)
signal-integrity model 74ACT240PC
pins: 1 ~{OE}1 (in), 2 A1 (in), 3 ~{Y}5 (hiz), 4 A2 (in), 5 ~{Y}6 (hiz), 6 A3 (in), 7 ~{Y}7 (hiz), 8 A4 (in), 9 ~{Y}8 (hiz), 10 GND (power), 11 A8 (in), 12 ~{Y}4 (hiz), 13 A7 (in), 14 ~{Y}3 (hiz), 15 A6 (in), 16 ~{Y}2 (hiz), 17 A5 (in), 18 ~{Y}1 (hiz), 19 ~{OE}2 (in), 20 VCC (power)

## 74ACT240SC
designator U?
Octal Buffer/Line Driver with 3-State Output
footprint M20B_N (SOIC, 20-Leads, Body 12.8x7.5mm, Pitch 1.27mm, IPC Medium Density)
footprint M20B_L (SOIC, 20-Leads, Body 12.8x7.5mm, Pitch 1.27mm, IPC High Density)
footprint M20B_M (SOIC, 20-Leads, Body 12.8x7.5mm, Pitch 1.27mm, IPC Low Density)
3D model M20B (20-Pin Small Outline Integrated Circuit 1.27 mm Pitch)
signal-integrity model 74ACT240SC
pins: 1 ~{OE}1 (in), 2 A1 (in), 3 ~{Y}5 (hiz), 4 A2 (in), 5 ~{Y}6 (hiz), 6 A3 (in), 7 ~{Y}7 (hiz), 8 A4 (in), 9 ~{Y}8 (hiz), 10 GND (power), 11 A8 (in), 12 ~{Y}4 (hiz), 13 A7 (in), 14 ~{Y}3 (hiz), 15 A6 (in), 16 ~{Y}2 (hiz), 17 A5 (in), 18 ~{Y}1 (hiz), 19 ~{OE}2 (in), 20 VCC (power)

## 74ACT240SJ
designator U?
Octal Buffer/Line Driver with 3-State Output
footprint M20D_N (SOP, 20-Leads, Body 12.6x5.3mm, Pitch 1.27mm, IPC Medium Density)
footprint M20D_L (SOP, 20-Leads, Body 12.6x5.3mm, Pitch 1.27mm, IPC High Density)
footprint M20D_M (SOP, 20-Leads, Body 12.6x5.3mm, Pitch 1.27mm, IPC Low Density)
3D model M20D (20-Pin Small Outline Package 1.27 mm Pitch)
signal-integrity model 74ACT240SJ
pins: 1 ~{OE}1 (in), 2 A1 (in), 3 ~{Y}5 (hiz), 4 A2 (in), 5 ~{Y}6 (hiz), 6 A3 (in), 7 ~{Y}7 (hiz), 8 A4 (in), 9 ~{Y}8 (hiz), 10 GND (power), 11 A8 (in), 12 ~{Y}4 (hiz), 13 A7 (in), 14 ~{Y}3 (hiz), 15 A6 (in), 16 ~{Y}2 (hiz), 17 A5 (in), 18 ~{Y}1 (hiz), 19 ~{OE}2 (in), 20 VCC (power)

## 74ACT241MTC
designator U?
Octal Buffer/Line Driver with 3-State Output
footprint MTC20_N (TSOP, 20-Leads, Body 6.5x4.4mm, Pitch 0.65mm, IPC Medium Density)
footprint MTC20_L (TSOP, 20-Leads, Body 6.5x4.4mm, Pitch 0.65mm, IPC High Density)
footprint MTC20_M (TSOP, 20-Leads, Body 6.5x4.4mm, Pitch 0.65mm, IPC Low Density)
3D model MTC20 (20-Pin Thin Small Outline Package 0.65 mm Pitch)
signal-integrity model 74ACT241MTC
pins: 1 ~{OE}1 (in), 2 A1 (in), 3 Y5 (hiz), 4 A2 (in), 5 Y6 (hiz), 6 A3 (in), 7 Y7 (hiz), 8 A4 (in), 9 Y8 (hiz), 10 GND (power), 11 A8 (in), 12 Y4 (hiz), 13 A7 (in), 14 Y3 (hiz), 15 A6 (in), 16 Y2 (hiz), 17 A5 (in), 18 Y1 (hiz), 19 OE2 (in), 20 VCC (power)

## 74ACT241PC
designator U?
Octal Buffer/Line Driver with 3-State Output
footprint N20A (DIP, 20-Leads, Row Spacing 7.62mm, Pitch 2.54mm, Body 26.07x6.6mm)
3D model N20A (DIP, 20-Pin, Row Spacing 7.62 mm, Pitch 2.54 mm)
signal-integrity model 74ACT241PC
pins: 1 ~{OE}1 (in), 2 A1 (in), 3 Y5 (hiz), 4 A2 (in), 5 Y6 (hiz), 6 A3 (in), 7 Y7 (hiz), 8 A4 (in), 9 Y8 (hiz), 10 GND (power), 11 A8 (in), 12 Y4 (hiz), 13 A7 (in), 14 Y3 (hiz), 15 A6 (in), 16 Y2 (hiz), 17 A5 (in), 18 Y1 (hiz), 19 OE2 (in), 20 VCC (power)

## 74ACT241SC
designator U?
Octal Buffer/Line Driver with 3-State Output
footprint M20B_N (SOIC, 20-Leads, Body 12.8x7.5mm, Pitch 1.27mm, IPC Medium Density)
footprint M20B_L (SOIC, 20-Leads, Body 12.8x7.5mm, Pitch 1.27mm, IPC High Density)
footprint M20B_M (SOIC, 20-Leads, Body 12.8x7.5mm, Pitch 1.27mm, IPC Low Density)
3D model M20B (20-Pin Small Outline Integrated Circuit 1.27 mm Pitch)
signal-integrity model 74ACT241SC
pins: 1 ~{OE}1 (in), 2 A1 (in), 3 Y5 (hiz), 4 A2 (in), 5 Y6 (hiz), 6 A3 (in), 7 Y7 (hiz), 8 A4 (in), 9 Y8 (hiz), 10 GND (power), 11 A8 (in), 12 Y4 (hiz), 13 A7 (in), 14 Y3 (hiz), 15 A6 (in), 16 Y2 (hiz), 17 A5 (in), 18 Y1 (hiz), 19 OE2 (in), 20 VCC (power)

## 74ACT241SJ
designator U?
Octal Buffer/Line Driver with 3-State Output
footprint M20D_N (SOP, 20-Leads, Body 12.6x5.3mm, Pitch 1.27mm, IPC Medium Density)
footprint M20D_L (SOP, 20-Leads, Body 12.6x5.3mm, Pitch 1.27mm, IPC High Density)
footprint M20D_M (SOP, 20-Leads, Body 12.6x5.3mm, Pitch 1.27mm, IPC Low Density)
3D model M20D (20-Pin Small Outline Package 1.27 mm Pitch)
signal-integrity model 74ACT241SJ
pins: 1 ~{OE}1 (in), 2 A1 (in), 3 Y5 (hiz), 4 A2 (in), 5 Y6 (hiz), 6 A3 (in), 7 Y7 (hiz), 8 A4 (in), 9 Y8 (hiz), 10 GND (power), 11 A8 (in), 12 Y4 (hiz), 13 A7 (in), 14 Y3 (hiz), 15 A6 (in), 16 Y2 (hiz), 17 A5 (in), 18 Y1 (hiz), 19 OE2 (in), 20 VCC (power)

## 74ACT244MSA
designator U?
Octal Buffer/Line Driver with 3-State Output
footprint MSA20_N (SOP, 20-Leads, Body 7.3x5.3mm, Pitch 0.65mm, IPC Medium Density)
footprint MSA20_L (SOP, 20-Leads, Body 7.3x5.3mm, Pitch 0.65mm, IPC High Density)
footprint MSA20_M (SOP, 20-Leads, Body 7.3x5.3mm, Pitch 0.65mm, IPC Low Density)
3D model MSA20 (20-Pin Small Outline Package 0.65 mm Pitch)
signal-integrity model 74ACT244MSA
pins: 1 ~{OE}1 (in), 2 A1 (in), 3 Y5 (hiz), 4 A2 (in), 5 Y6 (hiz), 6 A3 (in), 7 Y7 (hiz), 8 A4 (in), 9 Y8 (hiz), 10 GND (power), 11 A8 (in), 12 Y4 (hiz), 13 A7 (in), 14 Y3 (hiz), 15 A6 (in), 16 Y2 (hiz), 17 A5 (in), 18 Y1 (hiz), 19 ~{OE}2 (in), 20 VCC (power)

## 74ACT244MTC
designator U?
Octal Buffer/Line Driver with 3-State Output
footprint MTC20_N (TSOP, 20-Leads, Body 6.5x4.4mm, Pitch 0.65mm, IPC Medium Density)
footprint MTC20_L (TSOP, 20-Leads, Body 6.5x4.4mm, Pitch 0.65mm, IPC High Density)
footprint MTC20_M (TSOP, 20-Leads, Body 6.5x4.4mm, Pitch 0.65mm, IPC Low Density)
3D model MTC20 (20-Pin Thin Small Outline Package 0.65 mm Pitch)
signal-integrity model 74ACT244MTC
pins: 1 ~{OE}1 (in), 2 A1 (in), 3 Y5 (hiz), 4 A2 (in), 5 Y6 (hiz), 6 A3 (in), 7 Y7 (hiz), 8 A4 (in), 9 Y8 (hiz), 10 GND (power), 11 A8 (in), 12 Y4 (hiz), 13 A7 (in), 14 Y3 (hiz), 15 A6 (in), 16 Y2 (hiz), 17 A5 (in), 18 Y1 (hiz), 19 ~{OE}2 (in), 20 VCC (power)

## 74ACT244PC
designator U?
Octal Buffer/Line Driver with 3-State Output
footprint N20A (DIP, 20-Leads, Row Spacing 7.62mm, Pitch 2.54mm, Body 26.07x6.6mm)
3D model N20A (DIP, 20-Pin, Row Spacing 7.62 mm, Pitch 2.54 mm)
signal-integrity model 74ACT244PC
pins: 1 ~{OE}1 (in), 2 A1 (in), 3 Y5 (hiz), 4 A2 (in), 5 Y6 (hiz), 6 A3 (in), 7 Y7 (hiz), 8 A4 (in), 9 Y8 (hiz), 10 GND (power), 11 A8 (in), 12 Y4 (hiz), 13 A7 (in), 14 Y3 (hiz), 15 A6 (in), 16 Y2 (hiz), 17 A5 (in), 18 Y1 (hiz), 19 ~{OE}2 (in), 20 VCC (power)

## 74ACT244SC
designator U?
Octal Buffer/Line Driver with 3-State Output
footprint M20B_N (SOIC, 20-Leads, Body 12.8x7.5mm, Pitch 1.27mm, IPC Medium Density)
footprint M20B_L (SOIC, 20-Leads, Body 12.8x7.5mm, Pitch 1.27mm, IPC High Density)
footprint M20B_M (SOIC, 20-Leads, Body 12.8x7.5mm, Pitch 1.27mm, IPC Low Density)
3D model M20B (20-Pin Small Outline Integrated Circuit 1.27 mm Pitch)
signal-integrity model 74ACT244SC
pins: 1 ~{OE}1 (in), 2 A1 (in), 3 Y5 (hiz), 4 A2 (in), 5 Y6 (hiz), 6 A3 (in), 7 Y7 (hiz), 8 A4 (in), 9 Y8 (hiz), 10 GND (power), 11 A8 (in), 12 Y4 (hiz), 13 A7 (in), 14 Y3 (hiz), 15 A6 (in), 16 Y2 (hiz), 17 A5 (in), 18 Y1 (hiz), 19 ~{OE}2 (in), 20 VCC (power)

## 74ACT244SJ
designator U?
Octal Buffer/Line Driver with 3-State Output
footprint M20D_N (SOP, 20-Leads, Body 12.6x5.3mm, Pitch 1.27mm, IPC Medium Density)
footprint M20D_L (SOP, 20-Leads, Body 12.6x5.3mm, Pitch 1.27mm, IPC High Density)
footprint M20D_M (SOP, 20-Leads, Body 12.6x5.3mm, Pitch 1.27mm, IPC Low Density)
3D model M20D (20-Pin Small Outline Package 1.27 mm Pitch)
signal-integrity model 74ACT244SJ
pins: 1 ~{OE}1 (in), 2 A1 (in), 3 Y5 (hiz), 4 A2 (in), 5 Y6 (hiz), 6 A3 (in), 7 Y7 (hiz), 8 A4 (in), 9 Y8 (hiz), 10 GND (power), 11 A8 (in), 12 Y4 (hiz), 13 A7 (in), 14 Y3 (hiz), 15 A6 (in), 16 Y2 (hiz), 17 A5 (in), 18 Y1 (hiz), 19 ~{OE}2 (in), 20 VCC (power)

## 74ACT541MTC
designator U?
Octal Buffer/Line Driver with 3-State Output
footprint MTC20_N (TSOP, 20-Leads, Body 6.5x4.4mm, Pitch 0.65mm, IPC Medium Density)
footprint MTC20_L (TSOP, 20-Leads, Body 6.5x4.4mm, Pitch 0.65mm, IPC High Density)
footprint MTC20_M (TSOP, 20-Leads, Body 6.5x4.4mm, Pitch 0.65mm, IPC Low Density)
3D model MTC20 (20-Pin Thin Small Outline Package 0.65 mm Pitch)
signal-integrity model 74ACT541MTC
pins: 1 ~{OE}1 (in), 2 A1 (in), 3 A2 (in), 4 A3 (in), 5 A4 (in), 6 A5 (in), 7 A6 (in), 8 A7 (in), 9 A8 (in), 10 GND (power), 11 Y8 (hiz), 12 Y7 (hiz), 13 Y6 (hiz), 14 Y5 (hiz), 15 Y4 (hiz), 16 Y3 (hiz), 17 Y2 (hiz), 18 Y1 (hiz), 19 ~{OE}2 (in), 20 VCC (power)

## 74ACT541PC
designator U?
Octal Buffer/Line Driver with 3-State Output
footprint N20A (DIP, 20-Leads, Row Spacing 7.62mm, Pitch 2.54mm, Body 26.07x6.6mm)
3D model N20A (DIP, 20-Pin, Row Spacing 7.62 mm, Pitch 2.54 mm)
signal-integrity model 74ACT541PC
pins: 1 ~{OE}1 (in), 2 A1 (in), 3 A2 (in), 4 A3 (in), 5 A4 (in), 6 A5 (in), 7 A6 (in), 8 A7 (in), 9 A8 (in), 10 GND (power), 11 Y8 (hiz), 12 Y7 (hiz), 13 Y6 (hiz), 14 Y5 (hiz), 15 Y4 (hiz), 16 Y3 (hiz), 17 Y2 (hiz), 18 Y1 (hiz), 19 ~{OE}2 (in), 20 VCC (power)

## 74ACT541SC
designator U?
Octal Buffer/Line Driver with 3-State Output
footprint M20B_N (SOIC, 20-Leads, Body 12.8x7.5mm, Pitch 1.27mm, IPC Medium Density)
footprint M20B_L (SOIC, 20-Leads, Body 12.8x7.5mm, Pitch 1.27mm, IPC High Density)
footprint M20B_M (SOIC, 20-Leads, Body 12.8x7.5mm, Pitch 1.27mm, IPC Low Density)
3D model M20B (20-Pin Small Outline Integrated Circuit 1.27 mm Pitch)
signal-integrity model 74ACT541SC
pins: 1 ~{OE}1 (in), 2 A1 (in), 3 A2 (in), 4 A3 (in), 5 A4 (in), 6 A5 (in), 7 A6 (in), 8 A7 (in), 9 A8 (in), 10 GND (power), 11 Y8 (hiz), 12 Y7 (hiz), 13 Y6 (hiz), 14 Y5 (hiz), 15 Y4 (hiz), 16 Y3 (hiz), 17 Y2 (hiz), 18 Y1 (hiz), 19 ~{OE}2 (in), 20 VCC (power)

## 74ACTQ240QSC
designator U?
Octal Buffer/Line Driver with 3-State Output
footprint MQA20_N (SOP, 20-Leads, Body 8.7x3.9mm, Pitch 0.635mm, IPC Medium Density)
footprint MQA20_L (SOP, 20-Leads, Body 8.7x3.9mm, Pitch 0.635mm, IPC High Density)
footprint MQA20_M (SOP, 20-Leads, Body 8.7x3.9mm, Pitch 0.635mm, IPC Low Density)
3D model MQA20 (20-Pin Small Outline Package 0.635 mm Pitch)
pins: 1 ~{OE}1 (in), 2 A1 (in), 3 ~{Y}5 (hiz), 4 A2 (in), 5 ~{Y}6 (hiz), 6 A3 (in), 7 ~{Y}7 (hiz), 8 A4 (in), 9 ~{Y}8 (hiz), 10 GND (power), 11 A8 (in), 12 ~{Y}4 (hiz), 13 A7 (in), 14 ~{Y}3 (hiz), 15 A6 (in), 16 ~{Y}2 (hiz), 17 A5 (in), 18 ~{Y}1 (hiz), 19 ~{OE}2 (in), 20 VCC (power)

## 74ACTQ240SC
designator U?
Octal Buffer/Line Driver with 3-State Output
footprint M20B_N (SOIC, 20-Leads, Body 12.8x7.5mm, Pitch 1.27mm, IPC Medium Density)
footprint M20B_L (SOIC, 20-Leads, Body 12.8x7.5mm, Pitch 1.27mm, IPC High Density)
footprint M20B_M (SOIC, 20-Leads, Body 12.8x7.5mm, Pitch 1.27mm, IPC Low Density)
3D model M20B (20-Pin Small Outline Integrated Circuit 1.27 mm Pitch)
pins: 1 ~{OE}1 (in), 2 A1 (in), 3 ~{Y}5 (hiz), 4 A2 (in), 5 ~{Y}6 (hiz), 6 A3 (in), 7 ~{Y}7 (hiz), 8 A4 (in), 9 ~{Y}8 (hiz), 10 GND (power), 11 A8 (in), 12 ~{Y}4 (hiz), 13 A7 (in), 14 ~{Y}3 (hiz), 15 A6 (in), 16 ~{Y}2 (hiz), 17 A5 (in), 18 ~{Y}1 (hiz), 19 ~{OE}2 (in), 20 VCC (power)

## 74ACTQ240SJ
designator U?
Octal Buffer/Line Driver with 3-State Output
footprint M20D_N (SOP, 20-Leads, Body 12.6x5.3mm, Pitch 1.27mm, IPC Medium Density)
footprint M20D_L (SOP, 20-Leads, Body 12.6x5.3mm, Pitch 1.27mm, IPC High Density)
footprint M20D_M (SOP, 20-Leads, Body 12.6x5.3mm, Pitch 1.27mm, IPC Low Density)
3D model M20D (20-Pin Small Outline Package 1.27 mm Pitch)
pins: 1 ~{OE}1 (in), 2 A1 (in), 3 ~{Y}5 (hiz), 4 A2 (in), 5 ~{Y}6 (hiz), 6 A3 (in), 7 ~{Y}7 (hiz), 8 A4 (in), 9 ~{Y}8 (hiz), 10 GND (power), 11 A8 (in), 12 ~{Y}4 (hiz), 13 A7 (in), 14 ~{Y}3 (hiz), 15 A6 (in), 16 ~{Y}2 (hiz), 17 A5 (in), 18 ~{Y}1 (hiz), 19 ~{OE}2 (in), 20 VCC (power)

## 74ACTQ244MSA
designator U?
Octal Buffer/Line Driver with 3-State Output
footprint MSA20_N (SOP, 20-Leads, Body 7.3x5.3mm, Pitch 0.65mm, IPC Medium Density)
footprint MSA20_L (SOP, 20-Leads, Body 7.3x5.3mm, Pitch 0.65mm, IPC High Density)
footprint MSA20_M (SOP, 20-Leads, Body 7.3x5.3mm, Pitch 0.65mm, IPC Low Density)
3D model MSA20 (20-Pin Small Outline Package 0.65 mm Pitch)
pins: 1 ~{OE}1 (in), 2 A1 (in), 3 Y5 (hiz), 4 A2 (in), 5 Y6 (hiz), 6 A3 (in), 7 Y7 (hiz), 8 A4 (in), 9 Y8 (hiz), 10 GND (power), 11 A8 (in), 12 Y4 (hiz), 13 A7 (in), 14 Y3 (hiz), 15 A6 (in), 16 Y2 (hiz), 17 A5 (in), 18 Y1 (hiz), 19 ~{OE}2 (in), 20 VCC (power)

## 74ACTQ244PC
designator U?
Octal Buffer/Line Driver with 3-State Output
footprint N20A (DIP, 20-Leads, Row Spacing 7.62mm, Pitch 2.54mm, Body 26.07x6.6mm)
3D model N20A (DIP, 20-Pin, Row Spacing 7.62 mm, Pitch 2.54 mm)
pins: 1 ~{OE}1 (in), 2 A1 (in), 3 Y5 (hiz), 4 A2 (in), 5 Y6 (hiz), 6 A3 (in), 7 Y7 (hiz), 8 A4 (in), 9 Y8 (hiz), 10 GND (power), 11 A8 (in), 12 Y4 (hiz), 13 A7 (in), 14 Y3 (hiz), 15 A6 (in), 16 Y2 (hiz), 17 A5 (in), 18 Y1 (hiz), 19 ~{OE}2 (in), 20 VCC (power)

## 74ACTQ244QSC
designator U?
Octal Buffer/Line Driver with 3-State Output
footprint MQA20_N (SOP, 20-Leads, Body 8.7x3.9mm, Pitch 0.635mm, IPC Medium Density)
footprint MQA20_L (SOP, 20-Leads, Body 8.7x3.9mm, Pitch 0.635mm, IPC High Density)
footprint MQA20_M (SOP, 20-Leads, Body 8.7x3.9mm, Pitch 0.635mm, IPC Low Density)
3D model MQA20 (20-Pin Small Outline Package 0.635 mm Pitch)
pins: 1 ~{OE}1 (in), 2 A1 (in), 3 Y5 (hiz), 4 A2 (in), 5 Y6 (hiz), 6 A3 (in), 7 Y7 (hiz), 8 A4 (in), 9 Y8 (hiz), 10 GND (power), 11 A8 (in), 12 Y4 (hiz), 13 A7 (in), 14 Y3 (hiz), 15 A6 (in), 16 Y2 (hiz), 17 A5 (in), 18 Y1 (hiz), 19 ~{OE}2 (in), 20 VCC (power)

## 74ACTQ244SC
designator U?
Octal Buffer/Line Driver with 3-State Output
footprint M20B_N (SOIC, 20-Leads, Body 12.8x7.5mm, Pitch 1.27mm, IPC Medium Density)
footprint M20B_L (SOIC, 20-Leads, Body 12.8x7.5mm, Pitch 1.27mm, IPC High Density)
footprint M20B_M (SOIC, 20-Leads, Body 12.8x7.5mm, Pitch 1.27mm, IPC Low Density)
3D model M20B (20-Pin Small Outline Integrated Circuit 1.27 mm Pitch)
pins: 1 ~{OE}1 (in), 2 A1 (in), 3 Y5 (hiz), 4 A2 (in), 5 Y6 (hiz), 6 A3 (in), 7 Y7 (hiz), 8 A4 (in), 9 Y8 (hiz), 10 GND (power), 11 A8 (in), 12 Y4 (hiz), 13 A7 (in), 14 Y3 (hiz), 15 A6 (in), 16 Y2 (hiz), 17 A5 (in), 18 Y1 (hiz), 19 ~{OE}2 (in), 20 VCC (power)

## 74ACTQ244SJ
designator U?
Octal Buffer/Line Driver with 3-State Output
footprint M20D_N (SOP, 20-Leads, Body 12.6x5.3mm, Pitch 1.27mm, IPC Medium Density)
footprint M20D_L (SOP, 20-Leads, Body 12.6x5.3mm, Pitch 1.27mm, IPC High Density)
footprint M20D_M (SOP, 20-Leads, Body 12.6x5.3mm, Pitch 1.27mm, IPC Low Density)
3D model M20D (20-Pin Small Outline Package 1.27 mm Pitch)
pins: 1 ~{OE}1 (in), 2 A1 (in), 3 Y5 (hiz), 4 A2 (in), 5 Y6 (hiz), 6 A3 (in), 7 Y7 (hiz), 8 A4 (in), 9 Y8 (hiz), 10 GND (power), 11 A8 (in), 12 Y4 (hiz), 13 A7 (in), 14 Y3 (hiz), 15 A6 (in), 16 Y2 (hiz), 17 A5 (in), 18 Y1 (hiz), 19 ~{OE}2 (in), 20 VCC (power)

## 74ALS240A-1N
designator U?
Octal 3-State Bus Driver
footprint N20A (DIP, 20-Leads, Row Spacing 7.62mm, Pitch 2.54mm, Body 26.07x6.6mm)
3D model N20A (DIP, 20-Pin, Row Spacing 7.62 mm, Pitch 2.54 mm)
simulation model 74LS240 (SIMCODE)
signal-integrity model 74ALS240A-1N
pins: 1 ~{OE}1 (in), 2 A1 (in), 3 ~{Y}8 (hiz), 4 A2 (in), 5 ~{Y}7 (hiz), 6 A3 (in), 7 ~{Y}6 (hiz), 8 A4 (in), 9 ~{Y}5 (hiz), 10 GND (power), 11 A5 (in), 12 ~{Y}4 (hiz), 13 A6 (in), 14 ~{Y}3 (hiz), 15 A7 (in), 16 ~{Y}2 (hiz), 17 A8 (in), 18 ~{Y}1 (hiz), 19 ~{OE}2 (in), 20 VCC (power)

## 74ALS240A-1WM
designator U?
Octal 3-State Bus Driver
footprint M20B_N (SOIC, 20-Leads, Body 12.8x7.5mm, Pitch 1.27mm, IPC Medium Density)
footprint M20B_L (SOIC, 20-Leads, Body 12.8x7.5mm, Pitch 1.27mm, IPC High Density)
footprint M20B_M (SOIC, 20-Leads, Body 12.8x7.5mm, Pitch 1.27mm, IPC Low Density)
3D model M20B (20-Pin Small Outline Integrated Circuit 1.27 mm Pitch)
simulation model 74LS240 (SIMCODE)
signal-integrity model 74ALS240A-1WM
pins: 1 ~{OE}1 (in), 2 A1 (in), 3 ~{Y}8 (hiz), 4 A2 (in), 5 ~{Y}7 (hiz), 6 A3 (in), 7 ~{Y}6 (hiz), 8 A4 (in), 9 ~{Y}5 (hiz), 10 GND (power), 11 A5 (in), 12 ~{Y}4 (hiz), 13 A6 (in), 14 ~{Y}3 (hiz), 15 A7 (in), 16 ~{Y}2 (hiz), 17 A8 (in), 18 ~{Y}1 (hiz), 19 ~{OE}2 (in), 20 VCC (power)

## 74ALS244B-1N
designator U?
Octal 3-State Bus Driver
footprint N20A (DIP, 20-Leads, Row Spacing 7.62mm, Pitch 2.54mm, Body 26.07x6.6mm)
3D model N20A (DIP, 20-Pin, Row Spacing 7.62 mm, Pitch 2.54 mm)
simulation model 74LS244 (SIMCODE)
signal-integrity model 74ALS244B-1N
pins: 1 ~{OE}1 (in), 2 A1 (in), 3 Y8 (hiz), 4 A2 (in), 5 Y7 (hiz), 6 A3 (in), 7 Y6 (hiz), 8 A4 (in), 9 Y5 (hiz), 10 GND (power), 11 A5 (in), 12 Y4 (hiz), 13 A6 (in), 14 Y3 (hiz), 15 A7 (in), 16 Y2 (hiz), 17 A8 (in), 18 Y1 (hiz), 19 ~{OE}2 (in), 20 VCC (power)

## 74ALS244B-1WM
designator U?
Octal 3-State Bus Driver
footprint M20B_N (SOIC, 20-Leads, Body 12.8x7.5mm, Pitch 1.27mm, IPC Medium Density)
footprint M20B_L (SOIC, 20-Leads, Body 12.8x7.5mm, Pitch 1.27mm, IPC High Density)
footprint M20B_M (SOIC, 20-Leads, Body 12.8x7.5mm, Pitch 1.27mm, IPC Low Density)
3D model M20B (20-Pin Small Outline Integrated Circuit 1.27 mm Pitch)
simulation model 74LS244 (SIMCODE)
signal-integrity model 74ALS244B-1WM
pins: 1 ~{OE}1 (in), 2 A1 (in), 3 Y8 (hiz), 4 A2 (in), 5 Y7 (hiz), 6 A3 (in), 7 Y6 (hiz), 8 A4 (in), 9 Y5 (hiz), 10 GND (power), 11 A5 (in), 12 Y4 (hiz), 13 A6 (in), 14 Y3 (hiz), 15 A7 (in), 16 Y2 (hiz), 17 A8 (in), 18 Y1 (hiz), 19 ~{OE}2 (in), 20 VCC (power)

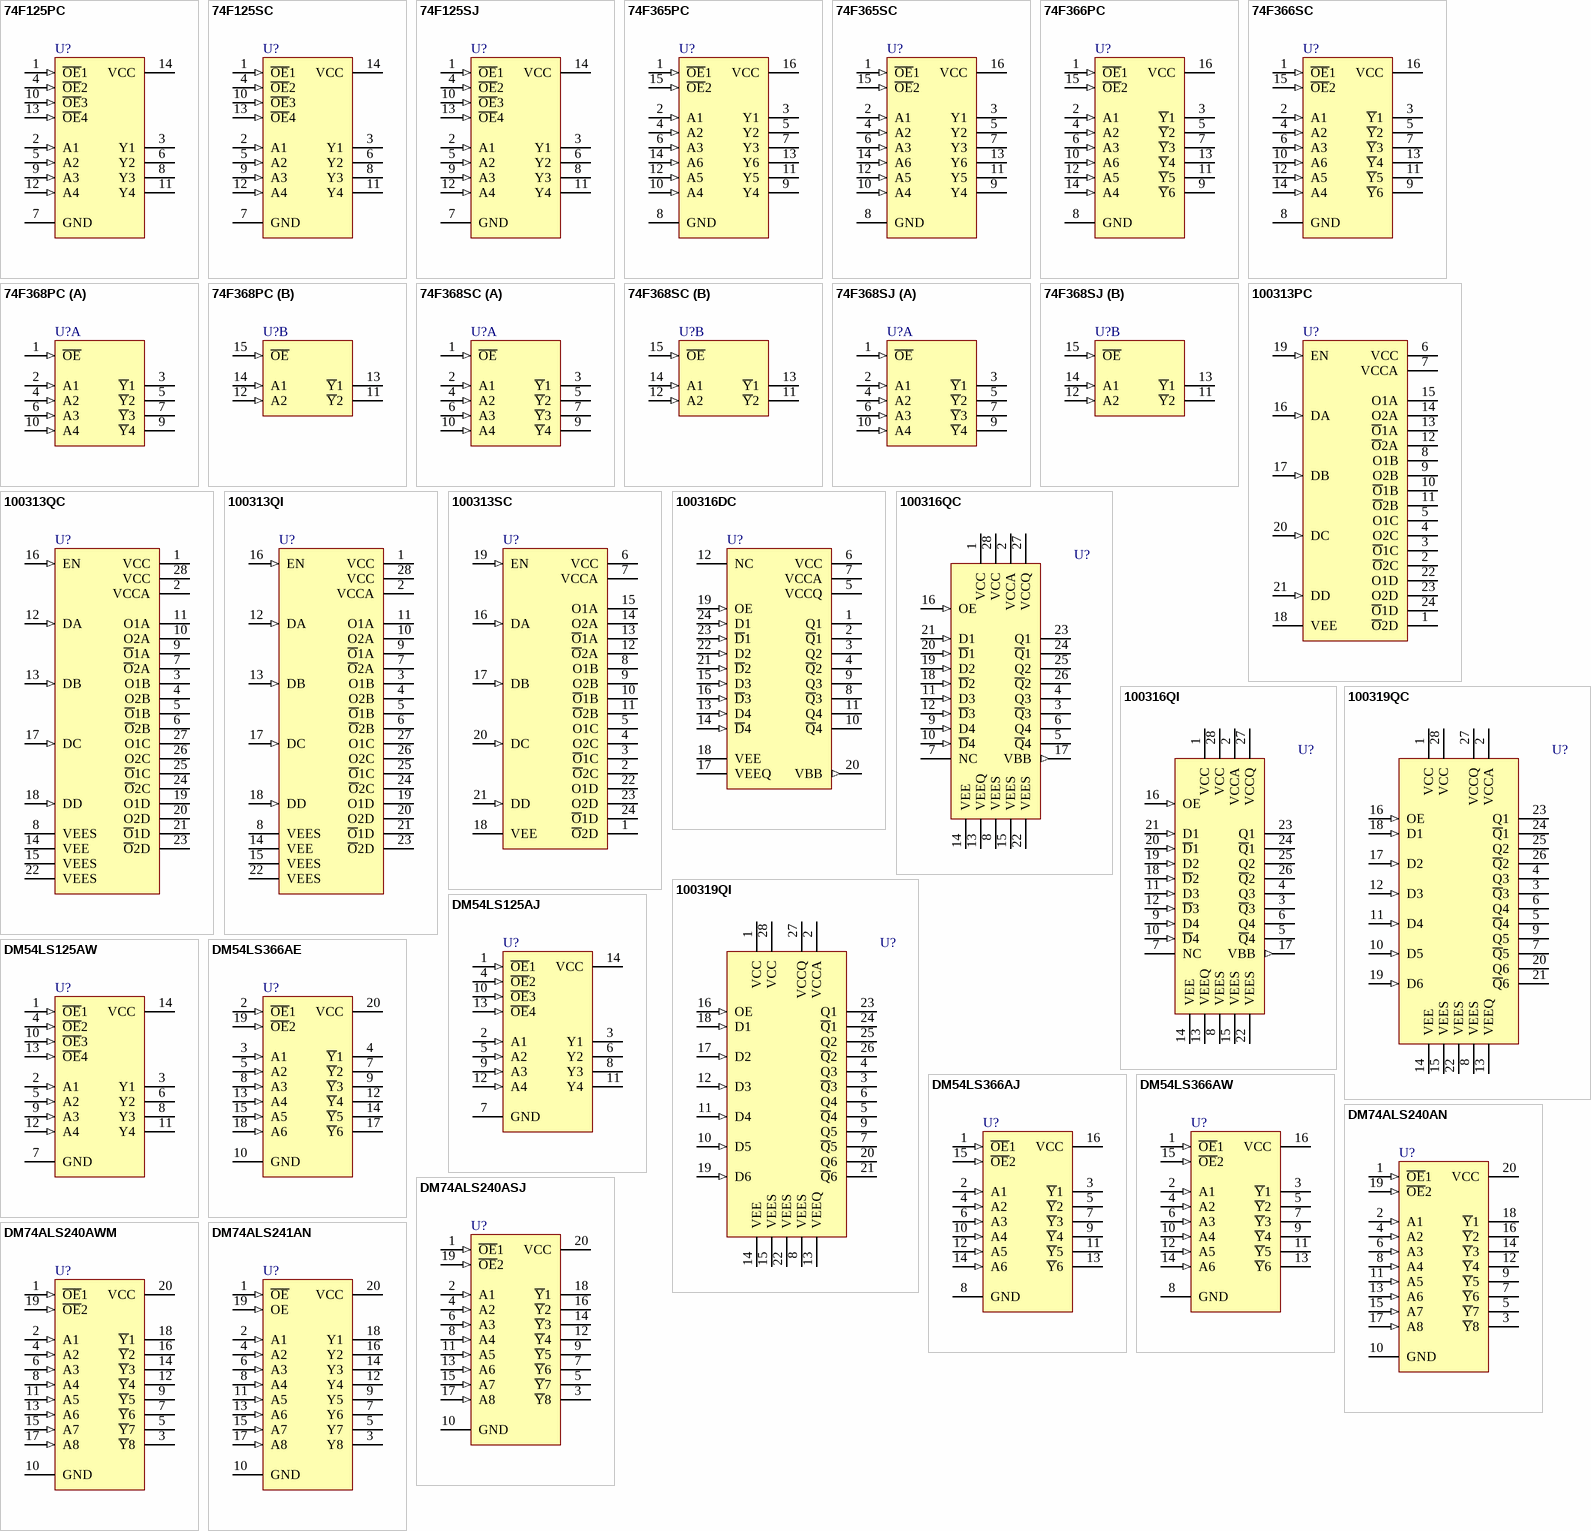
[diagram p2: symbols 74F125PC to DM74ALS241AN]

## 74F125PC
designator U?
3-State Quad Buffer
footprint N14A (DIP, 14-Leads, Row Spacing 7.62mm, Pitch 2.54mm, Body 19.18x6.35mm)
3D model N14A (DIP, 14-Pin, Row Spacing 7.62 mm, Pitch 2.54 mm)
simulation model 74F125x4 (SIMCODE)
signal-integrity model 74F125PC
pins: 1 ~{OE}1 (in), 2 A1 (in), 3 Y1 (hiz), 4 ~{OE}2 (in), 5 A2 (in), 6 Y2 (hiz), 7 GND (power), 8 Y3 (hiz), 9 A3 (in), 10 ~{OE}3 (in), 11 Y4 (hiz), 12 A4 (in), 13 ~{OE}4 (in), 14 VCC (power)

## 74F125SC
designator U?
3-State Quad Buffer
footprint M14A_N (SOIC, 14-Leads, Body 8.6x3.9mm, Pitch 1.27mm, IPC Medium Density)
footprint M14A_L (SOIC, 14-Leads, Body 8.6x3.9mm, Pitch 1.27mm, IPC High Density)
footprint M14A_M (SOIC, 14-Leads, Body 8.6x3.9mm, Pitch 1.27mm, IPC Low Density)
3D model M14A (14-Pin Small Outline Integrated Circuit 1.27 mm Pitch)
simulation model 74F125x4 (SIMCODE)
signal-integrity model 74F125SC
pins: 1 ~{OE}1 (in), 2 A1 (in), 3 Y1 (hiz), 4 ~{OE}2 (in), 5 A2 (in), 6 Y2 (hiz), 7 GND (power), 8 Y3 (hiz), 9 A3 (in), 10 ~{OE}3 (in), 11 Y4 (hiz), 12 A4 (in), 13 ~{OE}4 (in), 14 VCC (power)

## 74F125SJ
designator U?
3-State Quad Buffer
footprint M14D_N (SOP, 14-Leads, Body 10.1x5.3mm, Pitch 1.27mm, IPC Medium Density)
footprint M14D_L (SOP, 14-Leads, Body 10.1x5.3mm, Pitch 1.27mm, IPC High Density)
footprint M14D_M (SOP, 14-Leads, Body 10.1x5.3mm, Pitch 1.27mm, IPC Low Density)
3D model M14D (14-Pin Small Outline Package 1.27 mm Pitch)
simulation model 74F125x4 (SIMCODE)
signal-integrity model 74F125SJ
pins: 1 ~{OE}1 (in), 2 A1 (in), 3 Y1 (hiz), 4 ~{OE}2 (in), 5 A2 (in), 6 Y2 (hiz), 7 GND (power), 8 Y3 (hiz), 9 A3 (in), 10 ~{OE}3 (in), 11 Y4 (hiz), 12 A4 (in), 13 ~{OE}4 (in), 14 VCC (power)

## 74F365PC
designator U?
Hex Buffer/Driver with 3-State Output
footprint N16E (DIP, 16-Leads, Row Spacing 7.62mm, Pitch 2.54mm, Body 19.3x6.35mm)
3D model N16E (DIP, 16-Pin, Row Spacing 7.62 mm, Pitch 2.54 mm)
signal-integrity model 74F365PC
pins: 1 ~{OE}1 (in), 2 A1 (in), 3 Y1 (hiz), 4 A2 (in), 5 Y2 (hiz), 6 A3 (in), 7 Y3 (hiz), 8 GND (power), 9 Y4 (hiz), 10 A4 (in), 11 Y5 (hiz), 12 A5 (in), 13 Y6 (hiz), 14 A6 (in), 15 ~{OE}2 (in), 16 VCC (power)

## 74F365SC
designator U?
Hex Buffer/Driver with 3-State Output
footprint M16A_N (SOIC, 16-Leads, Body 9.9x3.9mm, Pitch 1.27mm, IPC Medium Density)
footprint M16A_L (SOIC, 16-Leads, Body 9.9x3.9mm, Pitch 1.27mm, IPC High Density)
footprint M16A_M (SOIC, 16-Leads, Body 9.9x3.9mm, Pitch 1.27mm, IPC Low Density)
3D model M16A (16-Pin Small Outline Integrated Circuit 1.27 mm Pitch)
signal-integrity model 74F365SC
pins: 1 ~{OE}1 (in), 2 A1 (in), 3 Y1 (hiz), 4 A2 (in), 5 Y2 (hiz), 6 A3 (in), 7 Y3 (hiz), 8 GND (power), 9 Y4 (hiz), 10 A4 (in), 11 Y5 (hiz), 12 A5 (in), 13 Y6 (hiz), 14 A6 (in), 15 ~{OE}2 (in), 16 VCC (power)

## 74F366PC
designator U?
Hex Inverter Buffer with 3-State Output
footprint N16E (DIP, 16-Leads, Row Spacing 7.62mm, Pitch 2.54mm, Body 19.3x6.35mm)
3D model N16E (DIP, 16-Pin, Row Spacing 7.62 mm, Pitch 2.54 mm)
signal-integrity model 74F366PC
pins: 1 ~{OE}1 (in), 2 A1 (in), 3 ~{Y}1 (hiz), 4 A2 (in), 5 ~{Y}2 (hiz), 6 A3 (in), 7 ~{Y}3 (hiz), 8 GND (power), 9 ~{Y}6 (hiz), 10 A6 (in), 11 ~{Y}5 (hiz), 12 A5 (in), 13 ~{Y}4 (hiz), 14 A4 (in), 15 ~{OE}2 (in), 16 VCC (power)

## 74F366SC
designator U?
Hex Inverter Buffer with 3-State Output
footprint M16A_N (SOIC, 16-Leads, Body 9.9x3.9mm, Pitch 1.27mm, IPC Medium Density)
footprint M16A_L (SOIC, 16-Leads, Body 9.9x3.9mm, Pitch 1.27mm, IPC High Density)
footprint M16A_M (SOIC, 16-Leads, Body 9.9x3.9mm, Pitch 1.27mm, IPC Low Density)
3D model M16A (16-Pin Small Outline Integrated Circuit 1.27 mm Pitch)
signal-integrity model 74F366SC
pins: 1 ~{OE}1 (in), 2 A1 (in), 3 ~{Y}1 (hiz), 4 A2 (in), 5 ~{Y}2 (hiz), 6 A3 (in), 7 ~{Y}3 (hiz), 8 GND (power), 9 ~{Y}6 (hiz), 10 A6 (in), 11 ~{Y}5 (hiz), 12 A5 (in), 13 ~{Y}4 (hiz), 14 A4 (in), 15 ~{OE}2 (in), 16 VCC (power)

## 74F368PC
designator U?
Hex Inverter Buffer with 3-State Output
footprint N16E (DIP, 16-Leads, Row Spacing 7.62mm, Pitch 2.54mm, Body 19.3x6.35mm)
3D model N16E (DIP, 16-Pin, Row Spacing 7.62 mm, Pitch 2.54 mm)
signal-integrity model 74F368PC
pins on every part: 8 GND (power) hidden to GND, 16 VCC (power) hidden to VCC
part A pins: 1 ~{OE} (in), 2 A1 (in), 3 ~{Y}1 (hiz), 4 A2 (in), 5 ~{Y}2 (hiz), 6 A3 (in), 7 ~{Y}3 (hiz), 9 ~{Y}4 (hiz), 10 A4 (in)
part B pins: 11 ~{Y}2 (hiz), 12 A2 (in), 13 ~{Y}1 (hiz), 14 A1 (in), 15 ~{OE} (in)

## 74F368SC
designator U?
Hex Inverter Buffer with 3-State Output
footprint M16A_N (SOIC, 16-Leads, Body 9.9x3.9mm, Pitch 1.27mm, IPC Medium Density)
footprint M16A_L (SOIC, 16-Leads, Body 9.9x3.9mm, Pitch 1.27mm, IPC High Density)
footprint M16A_M (SOIC, 16-Leads, Body 9.9x3.9mm, Pitch 1.27mm, IPC Low Density)
3D model M16A (16-Pin Small Outline Integrated Circuit 1.27 mm Pitch)
signal-integrity model 74F368SC
pins on every part: 8 GND (power) hidden to GND, 16 VCC (power) hidden to VCC
part A pins: 1 ~{OE} (in), 2 A1 (in), 3 ~{Y}1 (hiz), 4 A2 (in), 5 ~{Y}2 (hiz), 6 A3 (in), 7 ~{Y}3 (hiz), 9 ~{Y}4 (hiz), 10 A4 (in)
part B pins: 11 ~{Y}2 (hiz), 12 A2 (in), 13 ~{Y}1 (hiz), 14 A1 (in), 15 ~{OE} (in)

## 74F368SJ
designator U?
Hex Inverter Buffer with 3-State Output
footprint M16D_N (SOP, 16-Leads, Body 10.1x5.3mm, Pitch 1.27mm, IPC Medium Density)
footprint M16D_L (SOP, 16-Leads, Body 10.1x5.3mm, Pitch 1.27mm, IPC High Density)
footprint M16D_M (SOP, 16-Leads, Body 10.1x5.3mm, Pitch 1.27mm, IPC Low Density)
3D model M16D (16-Pin Small Outline Package 1.27 mm Pitch)
signal-integrity model 74F368SJ
pins on every part: 8 GND (power) hidden to GND, 16 VCC (power) hidden to VCC
part A pins: 1 ~{OE} (in), 2 A1 (in), 3 ~{Y}1 (hiz), 4 A2 (in), 5 ~{Y}2 (hiz), 6 A3 (in), 7 ~{Y}3 (hiz), 9 ~{Y}4 (hiz), 10 A4 (in)
part B pins: 11 ~{Y}2 (hiz), 12 A2 (in), 13 ~{Y}1 (hiz), 14 A1 (in), 15 ~{OE} (in)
